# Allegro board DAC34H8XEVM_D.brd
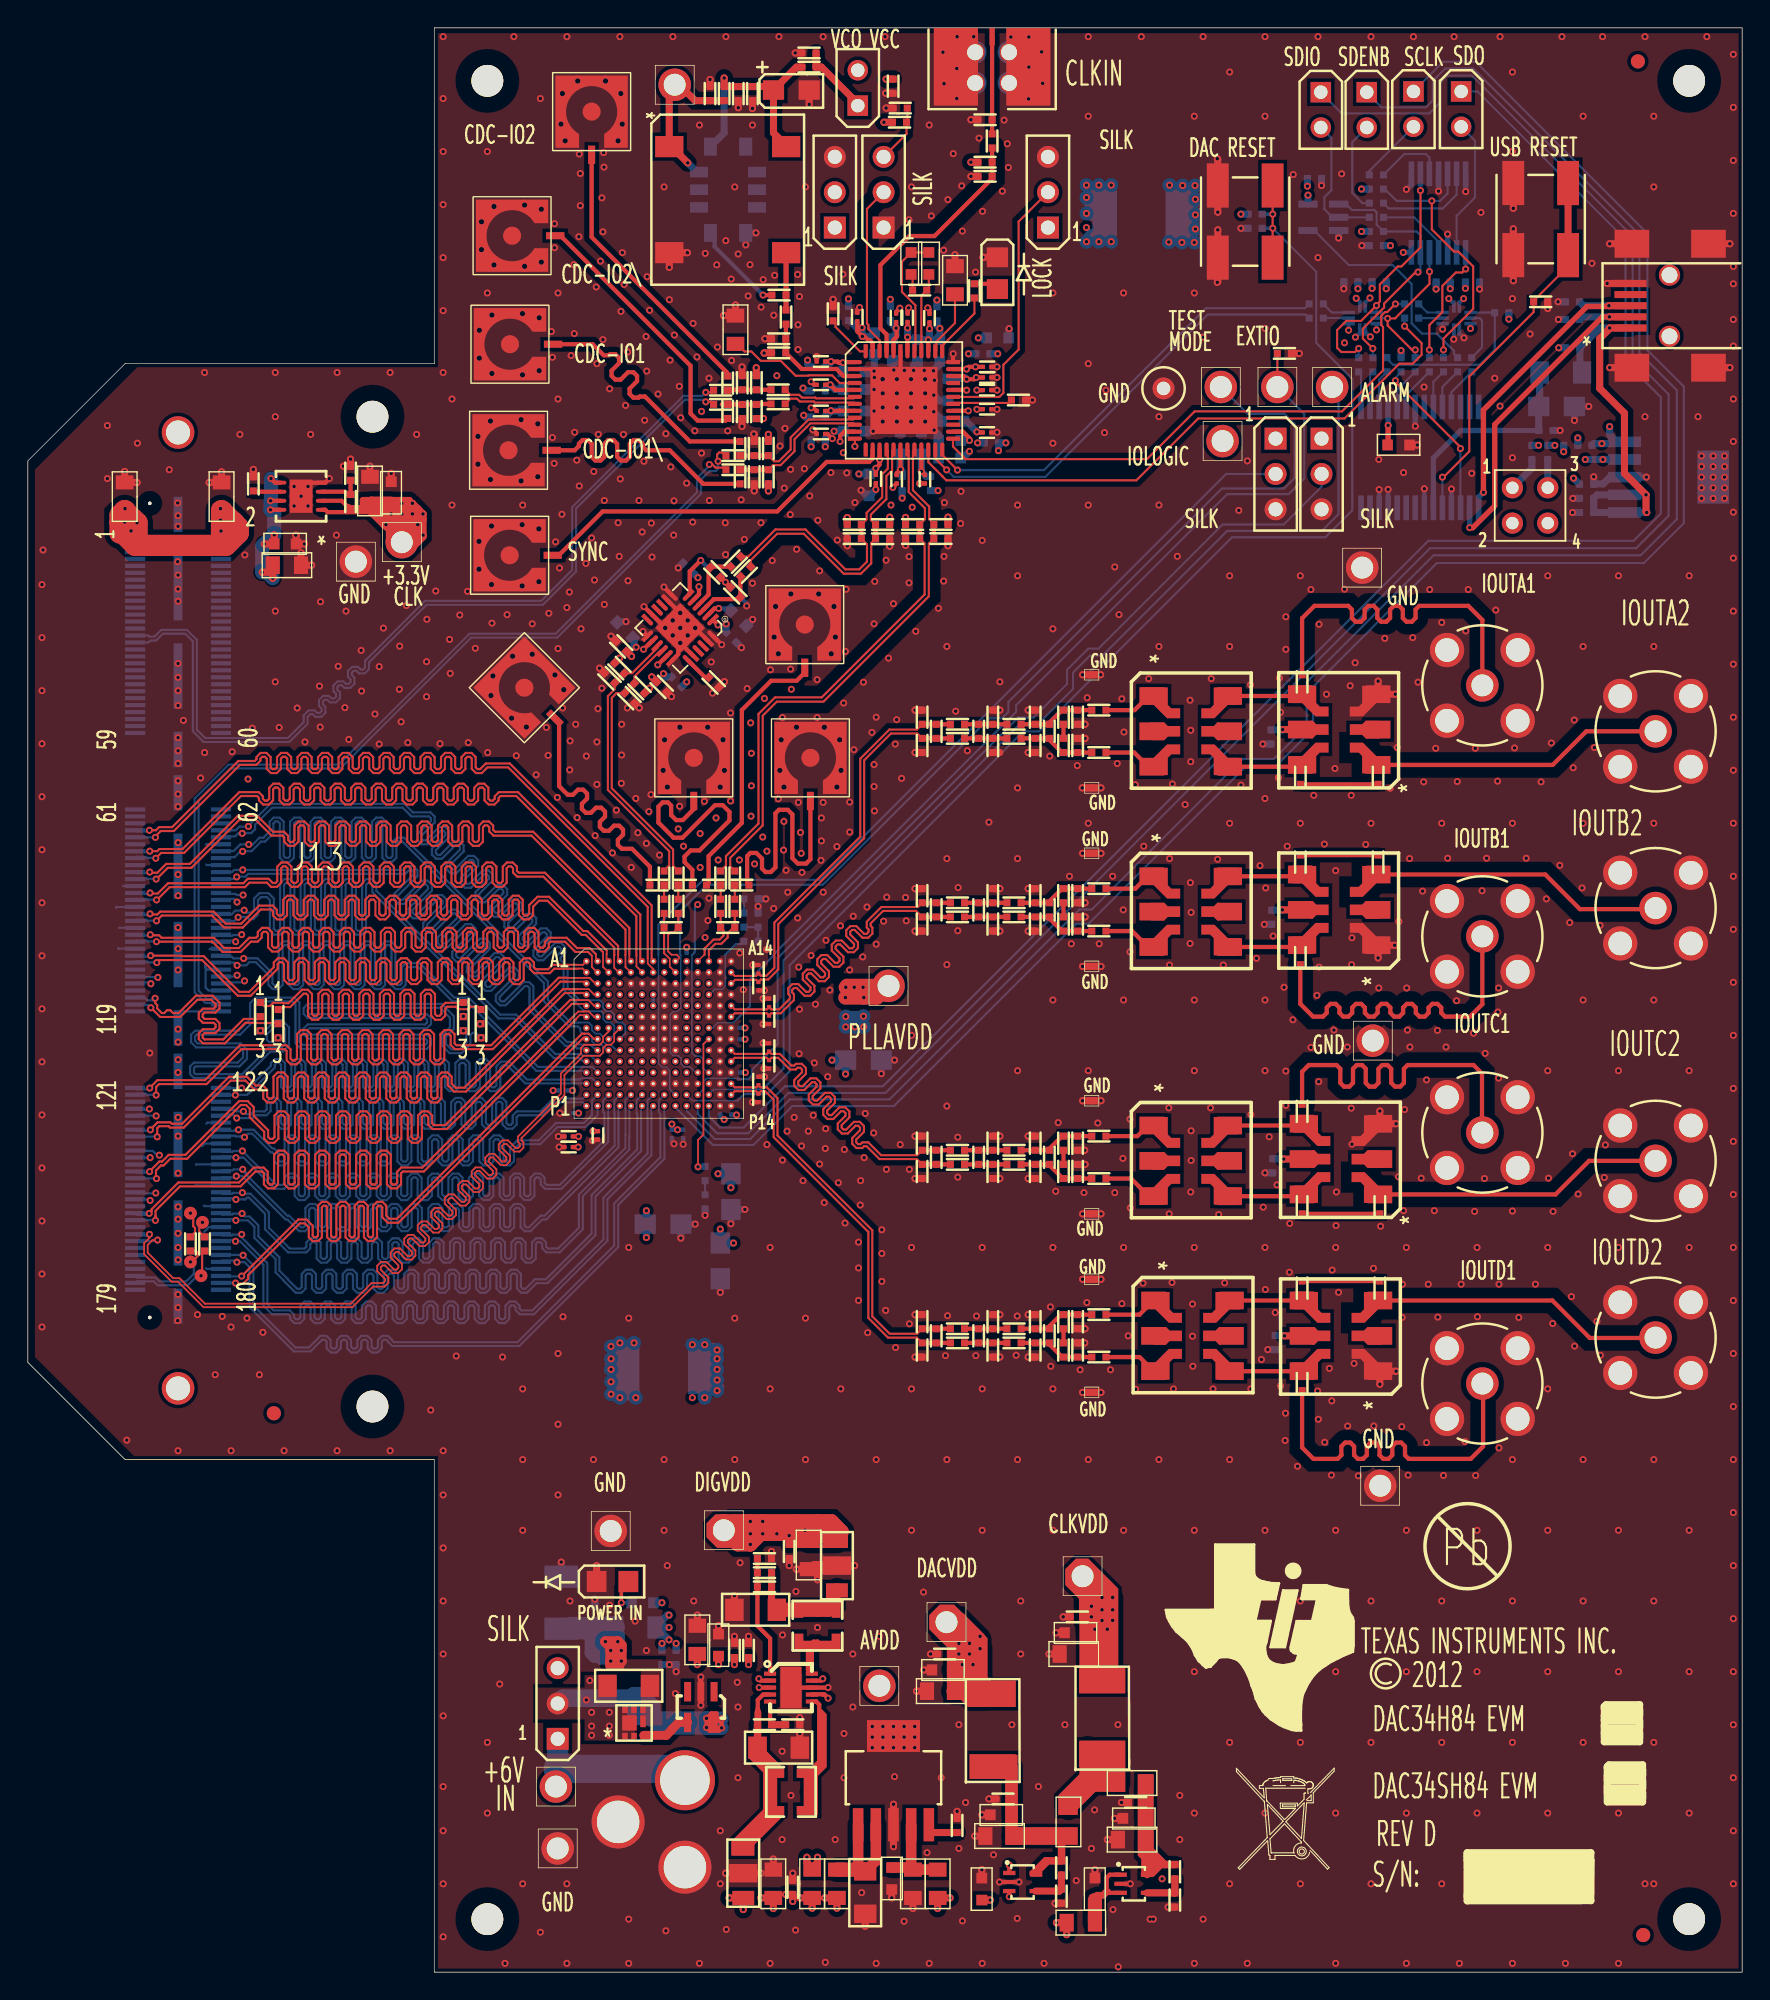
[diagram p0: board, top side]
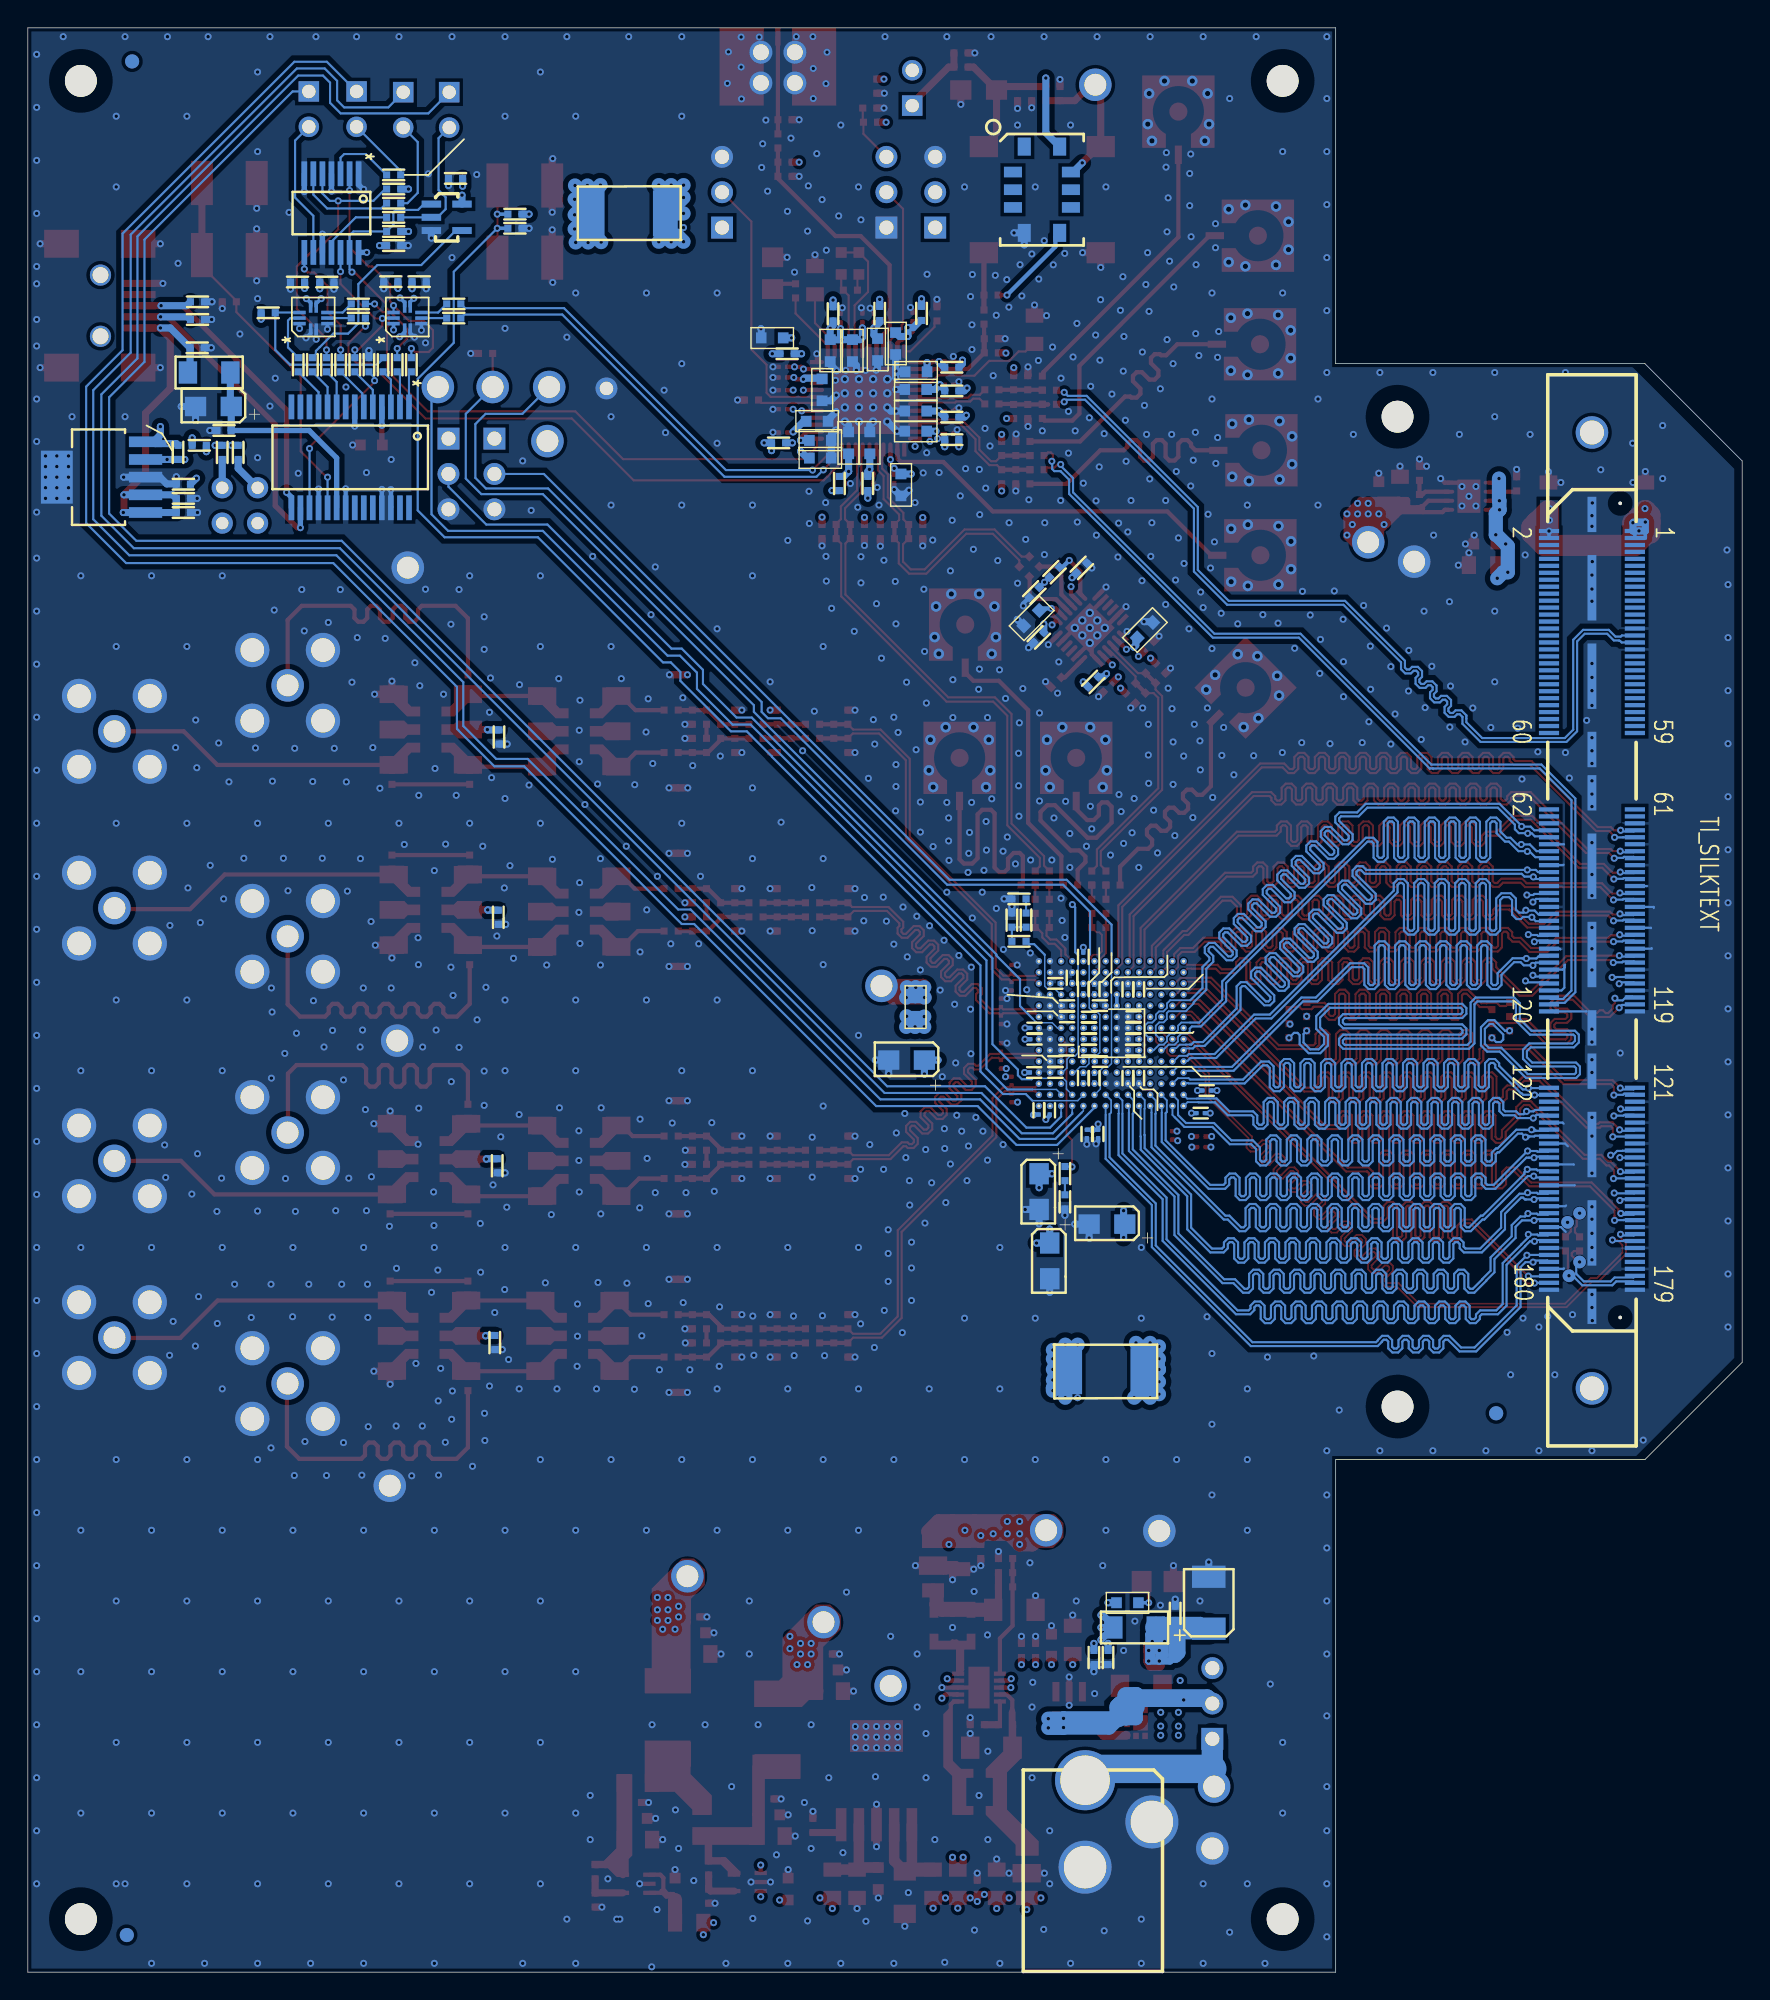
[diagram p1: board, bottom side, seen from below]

Outline 123.19 x 139.7 mm; copper layers: TOP, L2_GND, L3_PWR, L4_GND, L5_GND, L6_PWR, L7_GND, BOTTOM. Coordinates in mm from the lower left corner of the outline.
Outline path: 0,108.59 0,43.82 6.99,36.83 29.21,36.83 29.21,0 123.19,0 123.19,139.7 29.21,139.7 29.21,115.57 6.99,115.57 0,108.59

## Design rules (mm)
net group 50 OHM: nets N30997791 N30998469
net group DA0: nets DA0N DA0P
net group DA1: nets DA1N DA1P
net group DA2: nets DA2N DA2P
net group DA3: nets DA3N DA3P
net group DA4: nets DA4N DA4P
net group DA5: nets DA5N DA5P
net group DA6: nets DA6N DA6P
net group DA7: nets DA7N DA7P
net group DA8: nets DA8N DA8P
net group DA9: nets DA9N DA9P
net group DA10: nets DA10N DA10P
net group DA11: nets DA11N DA11P
net group DA12: nets DA12N DA12P
net group DA13: nets DA13N DA13P
net group DA14: nets DA14N DA14P
net group DA15: nets DA15N DA15P
net group DATACLK: nets DATACLKN DATACLKP
net group DATACLK-: nets DATACLK-N DATACLK-P
net group DB0: nets DB0N DB0P
net group DB1: nets DB1N DB1P
net group DB2: nets DB2N DB2P
net group DB3: nets DB3N DB3P
net group DB4: nets DB4N DB4P
net group DB5: nets DB5N DB5P
net group DB6: nets DB6N DB6P
net group DB7: nets DB7N DB7P
net group DB8: nets DB8N DB8P
net group DB9: nets DB9N DB9P
net group DB10: nets DB10N DB10P
net group DB11: nets DB11N DB11P
net group DB12: nets DB12N DB12P
net group DB13: nets DB13N DB13P
net group DB14: nets DB14N DB14P
net group DB15: nets DB15N DB15P
net group DCLK: nets DCLK-N DCLK-P
net group DP1: nets IOUTA1 IOUTA2
net group DP2: nets IOUTB1 IOUTB2
net group DP3: nets IOUTC1 IOUTC2
net group DP5: nets FIFO_OSTR FIFO_OSTRC
net group DP9: nets IOUTD1 IOUTD2
net group DP10: nets DCLKN DCLKP
net group FIFO_ISTR: nets FIFO_ISTRN FIFO_ISTRP
net group FPGA_CLKOUT: nets FPGA_CLKOUTN FPGA_CLKOUTP
net group FPGA_CLKOUT2: nets FPGA_CLKOUT2_N FPGA_CLKOUT2_P
net group PARITY: nets PARITYN PARITYP
net group PWR: nets +5V_USB N27288450
net group SYNC: nets SYNCN SYNCP

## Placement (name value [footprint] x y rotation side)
C1  .01uF  [0402]  45.72 76.71 90 top
C2  .01uF  [0402]  46.74 76.71 90 top
C3  .01uF  [0402]  49.78 76.71 90 top
C4  .01uF  [0402]  50.8 76.71 90 top
C5  .22uF  [0201]  50.88 64.64 180 bottom
C6  .22uF  [0201]  50.85 67.84 180 bottom
C7  .22uF  [0201]  47.35 64.24 270 bottom
C8  .22uF  [0201]  47.35 70.64 90 bottom
C9  .22uF  [0201]  48.51 69.44 0 bottom
C10  .22uF  [0201]  48.56 66.24 0 bottom
C11  .22uF  [0201]  50.85 67.03 180 bottom
C12  .22uF  [0201]  48.51 68.63 0 bottom
C13  .22uF  [0201]  46.15 65.43 180 bottom
C14  .22uF  [0201]  46.94 67.03 180 bottom
C15  .22uF  [0201]  50.55 61.93 90 bottom
C16  .22uF  [0201]  49.76 61.93 90 bottom
C17  .22uF  [0201]  46.94 66.24 180 bottom
C18  .22uF  [0201]  46.56 70.64 90 bottom
C19  .22uF  [0201]  46.56 64.24 270 bottom
C20  .22uF  [0201]  46.15 69.44 180 bottom
C21  .22uF  [0201]  46.94 67.84 180 bottom
C22  10uF  [TANT_A]  49.76 51.1 270 bottom
C23  .22uF  [0201]  46.94 68.63 180 bottom
C24  10uF  [TANT_A]  50.52 56.08 270 bottom
C25  .22uF  [0201]  40.97 60.12 270 top
C26  .22uF  [0201]  43.74 68.66 0 bottom
C27  .22uF  [0201]  38.91 61.72 180 bottom
C28  .22uF  [0201]  47.09 60.22 270 bottom
C29  .22uF  [0201]  38.48 63.35 180 bottom
C30  10uF  [TANT_A]  45.64 53.75 0 bottom
C31  .22uF  [0201]  43.76 66.24 0 bottom
C32  .22uF  [0201]  38.86 59.28 180 top
C33  .22uF  [0201]  46.28 60.22 270 bottom
C34  .1uF  [0402]  52.1 77.11 0 bottom
C35  1000pF  [0402]  52.48 75.72 90 bottom
C36  .1uF  [0201]  38.86 60.05 180 top
C37  .1uF  [0402]  90.42 116.31 0 top
C38  .22uF  [0201]  49.35 71.04 0 bottom
C39  .22uF  [0201]  49.35 65.43 0 bottom
C40  10uF  [TANT_A]  60.05 65.53 0 bottom
C41  .22uF  [0201]  43.76 67.03 0 bottom
C42  .22uF  [0201]  43.74 67.84 0 bottom
C43  .22uF  [0201]  44.15 64.24 270 bottom
C44  .22uF  [0201]  43.36 64.24 270 bottom
C45  .22uF  [0201]  43.36 70.61 90 bottom
C46  .22uF  [0201]  44.15 70.61 90 bottom
C47  1000pF  [0402]  88.06 125.3 180 bottom
C48  .1uF  [0201]  48.16 71.45 90 bottom
C49  .22uF  [0201]  47.35 72.95 270 bottom
C50  1000pF  [0402]  108.84 120.02 0 top
C51  .22uF  [0201]  49.35 64.64 0 bottom
C52  4.7uF  [0603]  63.47 122.77 270 top
C53  1000pF  [0402]  69.29 131.44 270 top
C54  .01uF  [0402]  50.78 99.22 135 bottom
C55  .27uF  [0603]  64.74 122.77 270 top
C56  .01uF  [0201]  63.22 118.87 90 top
C57  .01uF  [0201]  64.8 118.85 90 top
C58  .01uF  [0201]  62.39 118.87 90 top
C59  4.7uF  [0603]  63.93 116.51 270 bottom
C60  4.7uF  [0603]  65.53 116.51 270 bottom
C61  4.7uF  [0603]  62.13 116.59 270 bottom
C62  4.7uF  [0603]  42.91 96.42 135 bottom
C63  1uF  [0402]  57.86 119.02 270 top
C64  10uF  [0805]  66.62 121.56 270 top
C65  .01uF  [0201]  59.6 118.93 90 top
C66  4.7uF  [0603]  60.83 117.02 270 bottom
C67  .01uF  [0201]  56.99 114.05 180 top
C68  4.7uF  [0603]  59.39 113.72 0 bottom
C69  .01uF  [0201]  68.94 115.34 0 top
C70  .01uF  [0201]  68.94 114.58 0 top
C71  4.7uF  [0603]  66.12 113.69 270 bottom
C72  4.7uF  [0603]  69.7 117.42 0 bottom
C73  .01uF  [0201]  56.99 115.73 180 top
C74  4.7uF  [0603]  59.36 114.99 0 bottom
C75  10uF  [0805]  50.85 118.01 270 top
C76  .01uF  [0201]  68.93 110.62 0 top
C77  .01uF  [0201]  68.93 113.67 0 top
C78  .01uF  [0201]  68.93 112.3 0 top
C79  4.7uF  [0603]  66.24 110.06 180 bottom
C80  4.7uF  [0603]  66.47 111.43 180 bottom
C81  4.7uF  [0603]  66.24 108.79 180 bottom
C82  .01uF  [0201]  64.47 107.26 270 top
C83  4.7uF  [0603]  64.21 109.88 90 bottom
C84  .01uF  [0201]  56.99 110.52 180 top
C85  4.7uF  [0603]  59.39 110.72 0 bottom
C86  .01uF  [0201]  56.99 112.17 180 top
C87  4.7uF  [0603]  59.39 112.17 0 bottom
C88  .01uF  [0201]  62.43 107.26 270 top
C89  4.7uF  [0603]  62.69 109.88 90 bottom
C90  .01uF  [0402]  45.64 92.26 315 top
C91  10nF  [0402]  110.9 116.71 180 bottom
C92  .1uF  [0402]  109.22 110.77 0 bottom
C93  4.7uF  [TANT_A]  109.85 112.5 0 bottom
C94  .1uF  [0402]  97.23 121.46 0 bottom
C95  47pF  [0402]  110.87 118.75 180 bottom
C96  47pF  [0402]  110.87 120.02 180 bottom
C97  .1uF  [0402]  98.68 115.62 90 bottom
C98  .1uF  [0402]  92.58 128.88 0 bottom
C99  .01uF  [0402]  50.78 101.26 225 top
C100  .01uF  [0402]  51.5 100.54 225 top
C101  .01uF  [0402]  42.55 95.34 135 top
C102  .01uF  [0402]  50.63 95.81 315 bottom
C103  .01uF  [0402]  47.36 100.98 135 bottom
C104  4.7uF  [0603]  51.06 97.28 315 bottom
C111  1uF  [0603]  49.63 23.49 90 top
C112  .1uF  [0402]  50.77 23.24 90 top
C116  .1uF  [0402]  16.21 107.06 90 top
C117  1uF  [0603]  18.49 102.62 0 top
C118  1uF  [0603]  26.11 106.3 90 top
C127  .01uF  [0201]  60.93 107.29 270 top
C128  4.7uF  [0603]  60.45 106.86 270 bottom
C133  10uF  [0805]  53.57 6.35 90 top
C134  10uF  [0805]  56.11 29.97 270 top
C135  10uF  [0805]  18.62 101.09 0 top
C136  1uF  [0402]  111.89 105.89 180 bottom
C137  .1uF  [0402]  111.89 104.88 180 bottom
C138  15pF  [0402]  112.4 109.07 270 bottom
C139  .1uF  [0402]  94.95 121.46 180 bottom
C140  .1uF  [0402]  103.94 121.44 0 bottom
C141  .1uF  [0402]  101.57 121.44 180 bottom
C142  .1uF  [0402]  96.77 124.05 180 bottom
C143  10uF  [0805]  6.96 106.02 90 top
C144  10uF  [0805]  13.92 106.02 90 top
C145  10uF  [0805]  63.6 6.35 270 top
C146  10uF  [0805]  69.82 9.78 180 top
C147  10uF  [0805]  65.63 20.19 180 top
C148  10uF  [0805]  75.16 22.86 180 top
C149  10uF  [0805]  79.35 9.53 180 top
C152  47uF  [TANT_B]  38.33 26.54 90 bottom
C153  .1uF  [0402]  40.74 25.91 90 bottom
C154  1uF  [0402]  45.57 22.48 270 bottom
C155  10nF  [0402]  46.58 22.48 270 bottom
C161  10uF  [0805]  48.11 23.88 90 top
C162  10nF  [0402]  66.78 10.67 90 top
C163  2.2uF  [1206]  60.17 5.71 270 top
C164  1uF  [0603]  62.08 6.73 270 top
C165  22uF  [1206]  53.95 16.13 0 top
C166  33pF  [0402]  52.81 27.69 180 top
C167  22uF  [1206]  52.3 26.04 180 top
C169  2.2uF  [0603]  68.55 5.97 90 top
C170  1uF  [0603]  65.76 21.72 180 top
C177  .1uF  [0402]  54.48 118.79 270 top
C178  100pF  [0402]  52.07 134.85 270 top
C179  4.7uF  [0402]  62.18 135.38 270 top
C180  .1uF  [0402]  56.01 137.9 180 top
C181  10uF  [TANT_A]  54.86 135.23 0 top
C182  .1uF  [0402]  51.05 134.85 270 top
C215  10uF  [0805]  24.59 106.43 90 top
C233  10nF  [0402]  54.71 30.1 270 top
C234  10nF  [0402]  54.97 6.22 90 top
C237  10nF  [0402]  51.79 23.24 90 top
C238  1uF  [0603]  75.29 24.38 180 top
C240  2.2uF  [0603]  76.68 5.97 90 top
C242  10nF  [0402]  75.29 25.53 180 top
C243  10nF  [0402]  65.76 22.86 180 top
C244  1uF  [0603]  69.95 11.3 180 top
C245  10nF  [0402]  69.95 12.45 180 top
C246  1uF  [0603]  79.48 11.05 180 top
C247  10nF  [0402]  79.48 12.19 180 top
C250  2.2uF  [0603]  98.5 109.73 0 top
C251  CAP NP_1  [0402]  64.26 44.83 90 top
C252  CAP NP_1  [0402]  69.34 44.83 90 top
C253  CAP NP_1  [0402]  72.39 44.83 90 top
C254  3.3pF  [0402]  73.41 45.85 90 top
C255  3.3pF  [0402]  65.28 45.85 90 top
C256  3.3pF  [0402]  68.33 45.85 90 top
C257  CAP NP_1  [0402]  69.34 46.86 90 top
C258  CAP NP_1  [0402]  64.26 46.86 90 top
C259  CAP NP_1  [0402]  72.39 46.86 90 top
C260  CAP NP_1  [0402]  69.34 57.66 90 top
C261  CAP NP_1  [0402]  64.26 57.66 90 top
C262  CAP NP_1  [0402]  72.39 57.66 90 top
C263  3.3pF  [0402]  65.28 58.67 90 top
C264  3.3pF  [0402]  68.33 58.67 90 top
C265  3.3pF  [0402]  73.41 58.67 90 top
C266  CAP NP_1  [0402]  64.26 59.69 90 top
C267  CAP NP_1  [0402]  69.34 59.69 90 top
C268  CAP NP_1  [0402]  72.39 59.69 90 top
C269  CAP NP_1  [0402]  64.26 75.44 90 top
C270  CAP NP_1  [0402]  69.34 75.44 90 top
C271  CAP NP_1  [0402]  72.39 75.44 90 top
C272  3.3pF  [0402]  65.28 76.45 90 top
C273  3.3pF  [0402]  68.33 76.45 90 top
C274  3.3pF  [0402]  73.41 76.45 90 top
C275  CAP NP_1  [0402]  64.26 77.47 90 top
C276  CAP NP_1  [0402]  69.34 77.47 90 top
C277  CAP NP_1  [0402]  72.39 77.47 90 top
C278  CAP NP_1  [0402]  64.26 88.27 90 top
C279  CAP NP_1  [0402]  69.34 88.27 90 top
C280  CAP NP_1  [0402]  72.39 88.27 90 top
C281  3.3pF  [0402]  65.28 89.28 90 top
C282  3.3pF  [0402]  68.33 89.28 90 top
C283  3.3pF  [0402]  73.41 89.28 90 top
C284  CAP NP_1  [0402]  64.26 90.3 90 top
C285  CAP NP_1  [0402]  69.34 90.3 90 top
C286  CAP NP_1  [0402]  72.39 90.3 90 top
D1  LED green  [LED_0805]  69.67 122.07 90 top
D2  Blue  [LED_0805]  42.01 28.07 180 top
F3  2 AMP 63V FAST SMD  [1206]  43.18 20.57 0 top
FB1  1.5K @ 100MHz  [0603]  59.41 69.34 270 bottom
FB3  120  [0402]  61.98 119.05 270 bottom
FB4  1K  [0402]  65.33 119.02 270 bottom
FB5  120  [0402]  58.97 119.05 270 bottom
FB6  1K  [0402]  56.92 113.61 0 bottom
FB7  1K  [0402]  68.5 116.28 180 bottom
FB8  120  [0402]  56.92 115.32 0 bottom
FB9  120  [0402]  69.11 109.88 180 bottom
FB10  120  [0402]  64.87 107.09 90 bottom
FB11  120  [0402]  56.92 110.11 0 bottom
FB12  120  [0402]  56.92 111.73 0 bottom
FB13  120  [0402]  62.83 106.84 270 bottom
FB14  68 OHM @ 100MHz  [1206]  110.16 114.94 0 bottom
FB15  120  [0402]  46.72 92.62 315 bottom
FB20  68 OHM @ 100MHz  [1206]  43.66 24.76 180 bottom
FB22  1K  [1810]  45.69 43.18 180 bottom
FB24  1K  [1810]  80.01 126.37 0 bottom
FB25  1K  [0402]  56.26 136.88 0 top
FB30  27uF  [1206_BEAD_NFM31P]  58.14 29.21 90 top
FB31  27uF  [1206_BEAD_NFM31P]  51.41 7.11 270 top
FB34  1K  [1810]  69.32 17.4 90 top
FB35  1K  [1810]  77.19 18.29 90 top
J1  SMA_PCB_THVT  [SMA_THVT_312X312]  104.52 42.29 0 top
J2  SMA_PCB_THVT  [SMA_THVT_312X312]  116.97 45.59 0 top
J3  SMA_PCB_THVT  [SMA_THVT_312X312]  116.97 58.29 0 top
J4  SMA_PCB_THVT  [SMA_THVT_312X312]  104.52 60.33 0 top
J5  SMA_PCB_THVT  [SMA_THVT_312X312]  104.52 74.42 0 top
J6  SMA_PCB_THVT  [SMA_THVT_312X312]  116.97 76.45 0 top
J7  SMA_PCB_THVT  [SMA_THVT_312X312]  116.97 89.15 0 top
J8  SMA_PCB_THVT  [SMA_THVT_312X312]  104.52 92.46 0 top
J9  SMA_END_JACK_RND  [SMA_SMEL_218X247_096]  69.29 139.7 0 top
J10  SMP_PCB_SMT  [SMP_B120]  40.51 133.68 0 top
J11  SMP_PCB_SMT  [SMP_B120]  34.8 124.76 90 top
J12  SMP_PCB_SMT  [SMP_B120]  34.65 116.97 90 top
J13  CON, SMVT, 180POS, HS GND PLANE, QTH  [CON_SMVT_180POS_QTH_SAMTEC_RT1]  8.76 105.5 270 bottom
J14  USB_MINI_AB  [CON_SMRT_USBMNE20_F]  118.62 119.74 180 top
J15  SMP_PCB_SMT  [SMP_B120]  34.54 109.35 90 top
J18  CONN JACK PWR  [CON_RAPC722_JACK_THVT_3]  47.22 10.67 180 bottom
J19  SMP_PCB_SMT  [SMP_B120]  34.62 101.8 90 top
J20  SMP_PCB_SMT  [SMP_B120]  35.68 92.29 45 top
J21  SMP_PCB_SMT  [SMP_B120]  47.85 87.25 0 top
J22  SMP_PCB_SMT  [SMP_B120]  55.83 96.82 0 top
J23  SMP_PCB_SMT  [SMP_B120]  56.24 87.25 0 top
JP2  Jumper_1x3_100_430L  [HDR_THVT_1X3_100_M]  89.66 110.19 0 top
JP3  Jumper_1x3_100_430L  [HDR_THVT_1X3_100_M]  92.96 110.19 0 top
JP4  Jumper_1x3_100_430L  [HDR_THVT_1X3_100_M]  61.49 125.35 180 top
JP5  Jumper_1x3_100_430L  [HDR_THVT_1X3_100_M]  73.3 125.35 180 top
JP6  Jumper_1x3_100_430L  [HDR_THVT_1X3_100_M]  57.99 125.35 180 top
JP7  HEADER_1x2_100_430L  [HDR_THVT_1X2_100_M]  59.64 134.11 180 top
JP8  HEADER_1x2_100_430L  [HDR_THVT_1X2_100_M]  103 135.13 0 top
JP9  HEADER_1x2_100_430L  [HDR_THVT_1X2_100_M]  99.57 135.13 0 top
JP10  Jumper_1x3_100_430L  [HDR_THVT_1X3_100_M]  38.07 16.76 180 top
JP11  JUMPER_2X2  [HDR2X2_100CTR]  106.68 106.65 0 top
JP12  HEADER_1x2_100_430L  [HDR_THVT_1X2_100_M]  96.22 135.08 0 top
JP13  HEADER_1x2_100_430L  [HDR_THVT_1X2_100_M]  92.91 135.08 0 top
L25  2.2uH  [LPS3015]  54.84 12.95 180 top
L26  2.2uH  [LPS3015]  56.74 24.89 90 top
L27  0  [0402]  66.68 45.21 180 top
L28  0  [0402]  70.74 45.21 180 top
L29  0  [0402]  66.68 46.23 180 top
L30  0  [0402]  70.74 46.23 180 top
L31  0  [0402]  66.68 58.04 180 top
L32  0  [0402]  70.74 58.04 180 top
L33  0  [0402]  70.74 59.05 180 top
L34  0  [0402]  66.68 59.05 180 top
L35  0  [0402]  70.74 75.82 180 top
L36  0  [0402]  66.68 75.82 180 top
L37  0  [0402]  66.68 76.84 180 top
L38  0  [0402]  70.74 76.84 180 top
L39  0  [0402]  70.74 88.65 180 top
L40  0  [0402]  66.68 88.65 180 top
L41  0  [0402]  66.68 89.66 180 top
L42  0  [0402]  70.74 89.66 180 top
NOREF  -  []  745.39 141.78 0 top
NOREF#2  -  []  29.21 139.7 0 top
NOREF#3  -  [unnamed#2]  115.7 137.29 0 top
NOREF#4  -  []  -9.7 77.7 0 top
NOREF#5  -  []  2.68 111.26 0 top
NOREF#6  -  [unnamed#3]  33.02 135.89 0 top
NOREF#7  -  []  29.21 0 90 top
NOREF#8  -  [unnamed#2]  17.68 40.16 0 top
NOREF#9  -  [unnamed#3]  33.02 3.81 0 top
NOREF#10  -  []  29.21 0 0 top
NOREF#11  -  []  133.65 20.93 0 top
NOREF#12  -  []  0 43.82 0 top
NOREF#13  -  [unnamed#3]  24.77 40.64 0 top
NOREF#14  -  [unnamed#3]  119.38 3.81 0 top
NOREF#15  -  []  0 43.82 0 top
NOREF#16  -  []  70.83 71.54 0 top
NOREF#17  -  []  33.02 3.81 90 top
NOREF#18  -  []  29.21 0 90 top
NOREF#19  -  []  -120.65 -165.1 0 top
NOREF#20  -  []  90.3 11.18 0 top
NOREF#21  -  []  -16.38 134.62 0 top
NOREF#22  -  [unnamed#2]  116.08 2.67 0 top
NOREF#23  -  [unnamed#3]  119.38 135.89 0 top
NOREF#24  -  []  33.02 3.81 90 top
NOREF#25  -  []  -128.27 -60.96 0 top
NOREF#26  -  [unnamed#3]  24.77 111.76 0 top
NOREF#27  -  [unnamed#2]  116.08 2.67 180 bottom
NOREF#28  -  [unnamed#2]  115.7 137.29 180 bottom
NOREF#29  -  [unnamed#2]  17.68 40.16 180 bottom
Q3  CSD17313Q2  [SON_8_2MMX2MM_0P65MM]  43.56 17.91 0 top
R4  0  [0402]  91.57 42.16 270 top
R5  100  [0402]  46.36 75.06 0 top
R6  100  [0402]  75.44 44.58 270 top
R7  49.9  [0402]  74.42 44.83 90 top
R9  0  [0402]  89.64 45.11 270 bottom
R10  100  [0402]  75.44 46.61 270 top
R12  0  [0402]  89.46 57.81 270 bottom
R13  0  [0402]  97.16 49.28 90 top
R14  0  [0402]  89.38 75.67 270 bottom
R15  100  [0402]  50.42 75.06 0 top
R16  0  [0402]  91.57 49.28 90 top
R18  0  [0402]  89.33 88.62 270 bottom
R20  0  [0402]  91.57 54.86 270 top
R21  100  [0402]  75.44 57.4 270 top
R22  49.9  [0402]  74.42 57.66 90 top
R23  100  [0402]  75.44 59.44 270 top
R24  0  [0402]  97.16 55.12 90 top
R25  0  [0402]  91.57 61.98 90 top
R28  0  [0402]  91.44 72.77 270 top
R29  100  [0402]  75.44 75.18 270 top
R30  49.9  [0402]  74.42 75.44 90 top
R31  100  [0402]  75.44 77.22 270 top
R32  0  [0402]  97.03 79.88 90 top
R33  49.9  [0201]  52.5 64.03 90 top
R34  0  [0402]  91.44 79.88 90 top
R35  49.9  [0201]  52.5 62.81 270 top
R36  0  [0402]  91.44 85.73 270 top
R37  100  [0402]  75.44 88.01 270 top
R38  49.9  [0402]  74.42 88.27 90 top
R39  100  [0402]  75.44 90.04 270 top
R40  0  [0402]  97.03 85.98 90 top
R41  49.9  [0201]  53.26 65.23 270 top
R42  0  [0402]  91.57 92.84 90 top
R43  1K  [0402]  51.46 75.72 90 bottom
R44  1.27K  [0402]  48.67 57.25 270 bottom
R45  10  [0402]  48.67 55.22 270 bottom
R46  1K  [0402]  88.06 126.31 180 bottom
R47  82.5  [0402]  68.91 130.05 0 top
R48  1.1K  [0402]  63.96 120.85 180 top
R49  49.9  [0402]  68.91 133.1 0 top
R50  130  [0402]  68.66 129.03 180 top
R51  82.5  [0402]  62.76 132.92 0 top
R52  301  [0402]  68.02 120.93 90 top
R53  130  [0402]  52.35 114.07 270 top
R54  22.1  [0402]  54.04 113.69 0 top
R55  0  [0402]  71.06 112.96 180 top
R56  82.5  [0402]  51.34 114.33 90 top
R57  130  [0402]  52.35 112.26 90 top
R58  22.1  [0402]  54.04 112.68 0 top
R59  82.5  [0402]  51.34 112.01 270 top
R60  130  [0402]  53.21 107.57 90 top
R61  130  [0402]  53.21 109.35 270 top
R62  130  [0402]  65.49 104.02 180 top
R63  130  [0402]  63.71 104.02 0 top
R64  82.5  [0402]  52.2 107.31 270 top
R65  82.5  [0402]  52.2 109.6 90 top
R66  150  [0402]  65.74 103 0 top
R67  150  [0402]  63.45 103 180 top
R68  130  [0402]  61.3 104.01 180 top
R69  130  [0402]  59.51 104.01 0 top
R70  0  [0402]  49.32 100.68 135 bottom
R71  150  [0402]  61.55 102.99 0 top
R72  150  [0402]  59.26 103 180 top
R73  10K  [0402]  105.79 119.23 180 bottom
R74  10K  [0402]  97.03 128.12 0 bottom
R75  22.1  [0402]  95.63 115.37 270 bottom
R76  22.1  [0402]  99.69 115.37 270 bottom
R77  22.1  [0402]  97.66 115.37 270 bottom
R78  22.1  [0402]  103.76 115.37 270 bottom
R79  22.1  [0402]  96.65 115.37 270 bottom
R80  22.1  [0402]  101.73 115.37 270 bottom
R81  22.1  [0402]  102.74 115.37 270 bottom
R82  22.1  [0402]  100.71 115.37 270 bottom
R83  10K  [0402]  97.03 125.07 0 bottom
R84  100  [0402]  96.77 129.13 180 bottom
R85  100  [0402]  92.46 119.86 180 bottom
R86  100  [0402]  96.77 127.1 180 bottom
R87  100  [0402]  96.77 126.09 180 bottom
R88  0  [0402]  49.91 113.67 0 top
R89  130  [0402]  43.86 92.35 135 top
R90  150  [0402]  43.32 91.45 315 top
R91  130  [0402]  42.6 93.6 315 top
R92  150  [0402]  41.71 93.06 135 top
R93  0  [0402]  49.91 112.65 0 top
R94  49.9  [0201]  53.26 66.45 90 top
R95  0  [0402]  53.85 120.5 180 top
R96  49.9  [0201]  53.26 69.65 90 top
R97  49.9  [0201]  53.26 68.43 270 top
R98  49.9  [0201]  52.5 70.84 270 top
R99  49.9  [0402]  74.42 46.86 90 top
R100  49.9  [0402]  74.42 59.69 90 top
R101  49.9  [0402]  74.42 77.47 90 top
R102  49.9  [0402]  74.42 90.3 90 top
R103  130  [0402]  62.81 133.93 0 top
R104  0  [0402]  77.09 44.2 0 top
R105  0  [0402]  77.09 47.24 0 top
R106  0  [0402]  77.09 57.02 0 top
R107  0  [0402]  77.09 60.07 0 top
R108  0  [0402]  77.09 74.8 0 top
R109  0  [0402]  77.09 77.85 0 top
R110  0  [0402]  77.09 87.63 0 top
R111  0  [0402]  77.09 90.68 0 top
R112  49.9  [0201]  52.5 72.06 90 top
R116  0  [0402]  50.55 108.97 180 top
R117  0  [0402]  50.55 107.95 180 top
R120  0  [0402]  50.29 112.27 90 top
R121  0  [0402]  50.29 114.05 270 top
R122  0  [0402]  45.34 78.11 0 top
R123  0  [0402]  47.12 78.11 180 top
R124  0  [0402]  49.4 78.11 0 top
R125  0  [0402]  51.18 78.11 180 top
R126  0  [0805]  75.67 3.56 180 top
R127  0  [0805]  79.35 13.59 180 top
R128  0  [0805]  74.78 10.79 270 top
R129  0  [0402]  51.18 109.35 270 top
R130  0  [0402]  51.18 107.31 270 top
R131  60.4K  [0402]  49.38 92.58 315 top
R133  0  [0402]  51.84 74.07 180 bottom
R134  30.1K  [0402]  112.14 106.91 0 bottom
R135  51.1K  [0402]  111 109.7 0 bottom
R136  19.6K  [0402]  109.22 109.07 270 bottom
R137  82K  [0402]  108.08 109.07 270 bottom
R138  100  [0402]  92.46 118.85 180 bottom
R139  100  [0402]  99.31 119.86 180 bottom
R140  100  [0402]  99.31 118.85 180 bottom
R143  10K  [0603]  44.17 26.54 0 bottom
R145  0  [0805]  56.36 6.35 270 top
R146  0  [0805]  58.14 6.35 90 top
R147  0  [0805]  65.38 6.35 270 top
R148  750K  [0402]  52.81 17.78 180 top
R149  0  [0402]  45.72 78.49 270 top
R150  191K  [0402]  53.06 28.7 0 top
R151  150K  [0402]  54.84 17.78 180 top
R152  0  [0402]  46.74 78.49 270 top
R153  182K  [0402]  52.81 29.72 180 top
R154  0  [0402]  49.78 78.49 270 top
R155  0  [0402]  50.8 78.49 270 top
R156  0  [0402]  11.68 52.45 90 top
R157  0  [0402]  12.7 52.45 90 top
R164  10K  [0402]  49.02 134.85 270 top
R165  10K  [0402]  50.04 135.1 90 top
R166  10K  [0402]  54.08 116.35 0 top
R167  10K  [0402]  54.08 117.36 0 top
R168  10K  [0402]  23.19 107.57 270 top
R170  30.9K  [0402]  23.19 105.54 270 top
R206  49.9  [0402]  50.75 99.23 135 top
R207  49.9  [0402]  49.31 100.67 135 top
R221  174K  [0402]  82.42 7.34 90 top
R257  174K  [0402]  74.27 7.62 90 top
R315  330K  [0402]  82.42 5.31 90 top
R316  330K  [0402]  74.27 5.59 90 top
SJP9  SMT Jumper_1x3  [0201_SMD_JUMPER3X1]  16.71 68.66 90 top
SJP10  SMT Jumper_1x3  [0201_SMD_JUMPER3X1]  17.98 68.15 90 top
SJP11  SMT Jumper_1x3  [0201_SMD_JUMPER3X1]  31.29 68.66 90 top
SJP12  SMT Jumper_1x3  [0201_SMD_JUMPER3X1]  32.56 68.15 90 top
SW1  SW RESET  [SW_SMVT_RESET]  87.48 125.78 0 top
SW2  USB RESET  [SW_SMVT_RESET]  108.71 125.96 0 top
T1  ADT4-1WT  [TFMR_6_RF_DUAL_FOOTPRINT]  94.36 45.72 90 top
T2  ADT4-1WT  [TFMR_6_RF_DUAL_FOOTPRINT]  94.36 58.42 90 top
T3  ADT4-1WT  [TFMR_6_RF_DUAL_FOOTPRINT]  94.23 76.33 90 top
T4  ADT4-1WT  [TFMR_6_RF_DUAL_FOOTPRINT]  94.23 89.28 90 top
T8  ETC1-1-13  [TFMR_6_RF_DUAL_FOOTPRINT]  83.69 45.72 270 top
T9  ETC1-1-13  [TFMR_6_RF_DUAL_FOOTPRINT]  83.57 58.29 270 top
T10  ETC1-1-13  [TFMR_6_RF_DUAL_FOOTPRINT]  83.57 76.2 270 top
T11  ETC1-1-13  [TFMR_6_RF_DUAL_FOOTPRINT]  83.57 89.15 270 top
TP1  Testloop_Black  [TESTPOINT_62DIA]  41.88 31.7 0 top
TP2  Testloop_White  [TESTPOINT_62DIA]  89.79 113.89 180 top
TP3  Testloop_Black  [TP_THVT_060_RND]  81.61 113.79 0 top
TP4  Testloop_White  [TESTPOINT_62DIA]  85.72 113.89 0 top
TP5  Testloop_White  [TESTPOINT_62DIA]  93.73 113.89 180 top
TP6  Testloop_Black  [TESTPOINT_62DIA]  95.89 100.91 0 top
TP7  Testloop_Black  [TESTPOINT_62DIA]  97.18 34.95 0 top
TP8  Testloop_Black  [TESTPOINT_62DIA]  23.57 101.35 0 top
TP9  Testloop_Black  [TESTPOINT_62DIA]  96.65 66.93 0 top
TP12  Testloop_Red  [TESTPOINT_62DIA]  37.95 13.34 0 top
TP13  Testloop_Black  [TESTPOINT_62DIA]  38.07 8.89 0 top
TP14  Testloop_White  [TESTPOINT_62DIA]  46.48 135.61 0 top
TP15  Testloop_Red  [TESTPOINT_62DIA]  50.01 31.75 90 top
TP16  Testloop_Red  [TESTPOINT_62DIA]  61.19 20.57 0 top
TP17  Testloop_Red  [TESTPOINT_62DIA]  26.87 102.74 270 top
TP18  Testloop_Red  [TESTPOINT_62DIA]  66.01 25.15 0 top
TP19  Testloop_Red  [TESTPOINT_62DIA]  75.79 28.45 0 top
TP25  Testloop_White  [TESTPOINT_62DIA]  85.85 110.01 0 top
TP26  Testloop_White  [TESTPOINT_62DIA]  61.85 70.87 0 top
TP27  GND PAD  [TESTPAD20_30]  76.45 80.39 0 top
TP28  GND PAD  [TESTPAD20_30]  76.45 72.26 0 top
TP29  GND PAD  [TESTPAD20_30]  76.45 41.66 0 top
TP30  GND PAD  [TESTPAD20_30]  76.45 49.78 0 top
TP31  GND PAD  [TESTPAD20_30]  76.45 93.22 180 top
TP32  GND PAD  [TESTPAD20_30]  76.45 85.09 0 top
TP33  GND PAD  [TESTPAD20_30]  76.45 62.61 0 top
TP34  GND PAD  [TESTPAD20_30]  76.45 54.48 0 top
U1  DAC34H84  [BGA14X14_PT8MM]  45.34 67.44 180 top
U2  CDCE62005  [QFN48_RGZ_RTC]  62.96 112.93 0 top
U3  FT245RL  [SSOP_28_413X220_26]  100.03 108.84 270 bottom
U4  74AVC2T245  [QFN10_RSW]  95.91 118.85 90 bottom
U5  74AVC2T245  [QFN10_RSW]  102.67 118.85 90 bottom
U6  CDCP1803  [QFN24_RGE_RTW]  46.88 96.58 225 top
U9  74LVC125A  [TSSOP_14_201X177_26]  101.37 126.39 270 bottom
U10  74LVC1G126  [DBV5]  93.09 126.09 180 bottom
U11  TPS62420  [SON_DRC_10]  54.84 20.45 0 top
U12  TPS79633  [SOT_223_6_TG]  62.84 13.97 0 top
U13  TPS71701  [SC70_DCK_G5]  71.48 6.48 0 top
U15  TPS7A8001DRB  [SON_8_124X124_PWRPAD_DRB]  19.63 106.05 180 top
U16  TCXO 19.2MHz  [SMD_XTAL_7X5MM_D75ASERIES]  50.32 128.07 180 bottom
U17  TCXO 19.2MHz  [OSC_4_SM_460X386]  50.29 127.36 270 top
U20  TPS79601  [SOT_223_6_TG]  118.11 108.05 90 bottom
U21  TPS2400  [DBV5]  48.36 19.05 270 top
U22  TPS71701  [SC70_DCK_G5]  79.48 6.35 0 top

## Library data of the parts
C1-C4 C34-C37 C47 C48 C50 C52 C53 C55-C90 C92 C94 C97-C104 C127 C128 C137 C139-C142 C154 C155 C165 C167 C169 C177 C178 C180 C182 C240 C250 = CAP NP_1: tolerance: 10%
C5-C10 C12-C19 C21 C25-C29 C31-C33 C38 C41 C43 C45 C164 C170 C179 C238 C244 C246 = CAP NP_1: tolerance: 20%
C11 C20 C23 C39 C42 C44 C46 C49 C51 = CAP0402_0: tolerance: 20%
C22 C24 C30 C40 = CAP POL-B_10uF_10V
C54 C112 C116 C133 C134 C143-C149 C153 C161 = CAP NP: tolerance: 10%
C91 = CAP0603: tolerance: 10%
C93 = CAP POL-B_10uF_10V: tolerance: 10%
C95 C96 = CAP0603: tolerance: 5%
C111 C117 C118 = CAP NP_2: tolerance: 20%
C135 C215 = CAP0201: tolerance: 20%
C136 = CAP NP_2: tolerance: 10%
C138 = CAP0603: tolerance: 2%
C152 = CAP POL: tolerance: 10%
C162 C233 C234 C237 C242 C243 C245 C247 = CAPACITOR_NP_4: tolerance: 10%
C163 = CAP POL-B: tolerance: 10%
C166 = CAP NP_1: tolerance: 2%
C181 = CAP POL-B_10uF_10V: tolerance: 20%
C251-C286 = CAP NP_1: tolerance: .25pF
D1 D2 = LED
F3 = FUSE/SM
FB1 FB3-FB15 FB20 FB25 = FERRITE_BEAD
FB22 FB24 FB34 FB35 = FERRITE_BEAD_0402_H
FB30 FB31 = BEAD_NFM31P
J1-J8 = SMA_PCB_THVT_142-0701-201_REC
J9 = SMA-END_JACK_142-0761-801_ROUND
J10-J12 J15 J19-J23 = SMP_PLUG_SMT
J13 = CON_SMVT_180POS_QTH_SAMTEC
J14 = USB_MINI_AB_MNE20-5G5P10
J18 = CONN JACK PWR
JP2-JP6 JP10 SJP9-SJP12 = Jumper_1x3_100_0
JP7-JP9 JP12 JP13 = JUMPER_1x2_100
JP11 = JUMPER_3X2_SMT_0
L25 L26 = IND1206
L27-L42 = IND0603_0: tolerance: 5%
Q3 = PWR_MOSFET_CSD17313Q2
R4 R9 R12-R14 R16 R18 R20 R24 R25 R28 R32 R34 R36 R40 R42 R55 R70 R88 R93 R95 R104-R111 R116 R117 R120-R125 R129 R130 R133 R145-R147 R149 R152 R154-R157 = R: tolerance: 5%
R5 R15 R143 = RES0603: tolerance: 1%
R6 R10 R21 R23 R29 R31 R33 R35 R37 R39 R41 R47-R53 R56 R57 R59-R69 R71-R74 R83-R87 R89-R92 R94 R96-R98 R103 R112 R131 R134-R140 R148 R150 R151 R153 R164-R168 R170 R221 R257 R315 R316 = R: tolerance: 1%
R7 R22 R30 R38 R99-R102 = Res_0603: tolerance: 1%
R43-R46 R54 R58 R75-R82 = R_0: tolerance: 1%
R126-R128 = RES0603: tolerance: 5%
R206 R207 = RESISTOR: tolerance: 1%
SW1 SW2 = SPST_PB_KT11P3JM_5
T1-T4 = ADT4-1T_0
T8-T11 = TFMR_5_ETC1-1-13_4
TP1-TP9 TP12-TP19 TP25 TP26 = TESTLOOP_BLACK
TP27-TP34 = TEST POINT_0
U1 = DAC34H84
U2 = ARES_0
U3 = FT245RL_0
U4 U5 = 74AVC2T245
U6 = CDCM1804_MLF24_3
U9 = 74LVC125A
U10 = 74LVC1G126
U11 = TPS62420_SON10_1
U12 U20 = TPS79633DCQ_1
U13 U22 = TPS79633DCQ_2
U15 = TPS7A8001DRB
U16 = OSC-VECTRON_2
U17 = OSC-VECTRON_0
U21 = TPS2400

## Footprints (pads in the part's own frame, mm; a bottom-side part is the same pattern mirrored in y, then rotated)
0201
  rect 0.305x0.305 smd: 1(-0.305,0) 2(0.305,0)
0201_SMD_JUMPER3X1
  rect 0.508x0.508 smd: 1(1.016,0) 2(0,0) 3(-1.016,0)
0402
  rect 0.508x0.508 smd: 1(-0.635,0) 2(0.381,0)
0603
  rect 0.762x0.787 smd: 1(-0.787,0) 2(0.787,0)
0805
  rect 1.016x1.27 smd: 1(-1.016,0) 2(1.016,0)
1206
  rect 1.321x1.6 smd: 1(-1.524,0) 2(1.524,0)
1206_BEAD_NFM31P
  rect 1.016x1.575 smd: 1(-1.778,0) 3(1.778,0)
  rect 1.321x2.032 smd: 2(0,0)
1810
  rect 1.778x3.302 smd: 1(-2.629,0) 2(2.629,0)
BGA14X14_PT8MM
  round 0.457 hole 0.203: A1(5.2,-5.2) A2(4.4,-5.2) A3(3.6,-5.2) A4(2.8,-5.2) A5(2,-5.2) A6(1.2,-5.2) A7(0.4,-5.2) A8(-0.4,-5.2) A9(-1.2,-5.2) A10(-2,-5.2) A11(-2.8,-5.2) A12(-3.6,-5.2) A13(-4.4,-5.2) A14(-5.2,-5.2) B1(5.2,-4.4) B2(4.4,-4.4) B3(3.6,-4.4) B4(2.8,-4.4) B5(2,-4.4) B6(1.2,-4.4) B7(0.4,-4.4) B8(-0.4,-4.4) B9(-1.2,-4.4) B10(-2,-4.4) B11(-2.8,-4.4) B12(-3.6,-4.4) B13(-4.4,-4.4) B14(-5.2,-4.4) C1(5.2,-3.6) C2(4.4,-3.6) C3(3.6,-3.6) C4(2.8,-3.6) C5(2,-3.6) C6(1.2,-3.6) C7(0.4,-3.6) C8(-0.4,-3.6) C9(-1.2,-3.6) C10(-2,-3.6) C11(-2.8,-3.6) C12(-3.6,-3.6) C13(-4.4,-3.6) C14(-5.2,-3.6) D1(5.2,-2.8) D2(4.4,-2.8) D3(3.6,-2.8) D4(2.8,-2.8) D5(2,-2.8) D6(1.2,-2.8) D7(0.4,-2.8) D8(-0.4,-2.8) D9(-1.2,-2.8) D10(-2,-2.8) D11(-2.8,-2.8) D12(-3.6,-2.8) D13(-4.4,-2.8) D14(-5.2,-2.8) E1(5.2,-2) E2(4.4,-2) E3(3.6,-2) E4(2.8,-2) E5(2,-2) E6(1.2,-2) E7(0.4,-2) E8(-0.4,-2) E9(-1.2,-2) E10(-2,-2) E11(-2.8,-2) E12(-3.6,-2) E13(-4.4,-2) E14(-5.2,-2) F1(5.2,-1.2) F2(4.4,-1.2) F3(3.6,-1.2) F4(2.8,-1.2) F5(2,-1.2) F6(1.2,-1.2) F7(0.4,-1.2) F8(-0.4,-1.2) F9(-1.2,-1.2) F10(-2,-1.2) F11(-2.8,-1.2) F12(-3.6,-1.2) F13(-4.4,-1.2) F14(-5.2,-1.2) G1(5.2,-0.4) G2(4.4,-0.4) G3(3.6,-0.4) G4(2.8,-0.4) G5(2,-0.4) G6(1.2,-0.4) G7(0.4,-0.4) G8(-0.4,-0.4) G9(-1.2,-0.4) G10(-2,-0.4) G11(-2.8,-0.4) G12(-3.6,-0.4) G13(-4.4,-0.4) G14(-5.2,-0.4) H1(5.2,0.4) H2(4.4,0.4) H3(3.6,0.4) H4(2.8,0.4) H5(2,0.4) H6(1.2,0.4) H7(0.4,0.4) H8(-0.4,0.4) H9(-1.2,0.4) H10(-2,0.4) H11(-2.8,0.4) H12(-3.6,0.4) H13(-4.4,0.4) H14(-5.2,0.4) J1(5.2,1.2) J2(4.4,1.2) J3(3.6,1.2) J4(2.8,1.2) J5(2,1.2) J6(1.2,1.2) J7(0.4,1.2) J8(-0.4,1.2) J9(-1.2,1.2) J10(-2,1.2) J11(-2.8,1.2) J12(-3.6,1.2) J13(-4.4,1.2) J14(-5.2,1.2) K1(5.2,2) K2(4.4,2) K3(3.6,2) K4(2.8,2) K5(2,2) K6(1.2,2) K7(0.4,2) K8(-0.4,2) K9(-1.2,2) K10(-2,2) K11(-2.8,2) K12(-3.6,2) K13(-4.4,2) K14(-5.2,2) L1(5.2,2.8) L2(4.4,2.8) L3(3.6,2.8) L4(2.8,2.8) L5(2,2.8) L6(1.2,2.8) L7(0.4,2.8) L8(-0.4,2.8) L9(-1.2,2.8) L10(-2,2.8) L11(-2.8,2.8) L12(-3.6,2.8) L13(-4.4,2.8) L14(-5.2,2.8) M1(5.2,3.6) M2(4.4,3.6) M3(3.6,3.6) M4(2.8,3.6) M5(2,3.6) M6(1.2,3.6) M7(0.4,3.6) M8(-0.4,3.6) M9(-1.2,3.6) M10(-2,3.6) M11(-2.8,3.6) M12(-3.6,3.6) M13(-4.4,3.6) M14(-5.2,3.6) N1(5.2,4.4) N2(4.4,4.4) N3(3.6,4.4) N4(2.8,4.4) N5(2,4.4) N6(1.2,4.4) N7(0.4,4.4) N8(-0.4,4.4) N9(-1.2,4.4) N10(-2,4.4) N11(-2.8,4.4) N12(-3.6,4.4) N13(-4.4,4.4) N14(-5.2,4.4) P1(5.2,5.2) P2(4.4,5.2) P3(3.6,5.2) P4(2.8,5.2) P5(2,5.2) P6(1.2,5.2) P7(0.4,5.2) P8(-0.4,5.2) P9(-1.2,5.2) P10(-2,5.2) P11(-2.8,5.2) P12(-3.6,5.2) P13(-4.4,5.2) P14(-5.2,5.2)
CON_RAPC722_JACK_THVT_3
  round 4.318 hole 3.556: 1(0,3.124)
  round 3.81 hole 3.048: 2(0,-3.124) 3(4.801,0.127)
CON_SMRT_USBMNE20_F
  round 1.524 hole 1.143 unplated: (0.65,2.2) (0.65,-2.2)
  rect 2.311x0.508 smd: 1(3.45,1.6) 2(3.45,0.8) 3(3.45,0) 4(3.45,-0.8) 5(3.45,-1.6)
  rect 2.489x2.007 smd: 6(-2.15,-4.45) 7(3.35,-4.45) 8(3.35,4.45) 9(-2.15,4.45)
CON_SMVT_180POS_QTH_SAMTEC_RT1
  round 2.337 hole 1.727: (-5.123,-2.032) (63.558,-2.032)
  round 0.254 hole 1.016 unplated: (-0.03,0) (58.466,0)
  rect 0.305x1.448 smd: 1(1.958,1.054) 2(1.958,-5.118) 3(2.459,1.054) 4(2.459,-5.118) 5(2.959,1.054) 6(2.959,-5.118) 7(3.459,1.054) 8(3.459,-5.118) 9(3.96,1.054) 10(3.96,-5.118) 11(4.46,1.054) 12(4.46,-5.118) 13(4.961,1.054) 14(4.961,-5.118) 15(5.461,1.054) 16(5.461,-5.118) 17(5.961,1.054) 18(5.961,-5.118) 19(6.462,1.054) 20(6.462,-5.118) 21(6.962,1.054) 22(6.962,-5.118) 23(7.463,1.054) 24(7.463,-5.118) 25(7.963,1.054) 26(7.963,-5.118) 27(8.463,1.054) 28(8.463,-5.118) 29(8.964,1.054) 30(8.964,-5.118) 31(9.464,1.054) 32(9.464,-5.118) 33(9.964,1.054) 34(9.964,-5.118) 35(10.465,1.054) 36(10.465,-5.118) 37(10.965,1.054) 38(10.965,-5.118) 39(11.466,1.054) 40(11.466,-5.118) 41(11.966,1.054) 42(11.966,-5.118) 43(12.466,1.054) 44(12.466,-5.118) 45(12.967,1.054) 46(12.967,-5.118) 47(13.467,1.054) 48(13.467,-5.118) 49(13.967,1.054) 50(13.967,-5.118) 51(14.468,1.054) 52(14.468,-5.118) 53(14.968,1.054) 54(14.968,-5.118) 55(15.469,1.054) 56(15.469,-5.118) 57(15.969,1.054) 58(15.969,-5.118) 59(16.469,1.054) 60(16.469,-5.118) 61(21.961,1.054) 62(21.961,-5.118) 63(22.461,1.054) 64(22.461,-5.118) 65(22.962,1.054) 66(22.962,-5.118) 67(23.462,1.054) 68(23.462,-5.118) 69(23.962,1.054) 70(23.962,-5.118) 71(24.463,1.054) 72(24.463,-5.118) 73(24.963,1.054) 74(24.963,-5.118) 75(25.463,1.054) 76(25.463,-5.118) 77(25.964,1.054) 78(25.964,-5.118) 79(26.464,1.054) 80(26.464,-5.118) 81(26.965,1.054) 82(26.965,-5.118) 83(27.465,1.054) 84(27.465,-5.118) 85(27.965,1.054) 86(27.965,-5.118) 87(28.466,1.054) 88(28.466,-5.118) 89(28.966,1.054) 90(28.966,-5.118) 91(29.467,1.054) 92(29.467,-5.118) 93(29.967,1.054) 94(29.967,-5.118) 95(30.467,1.054) 96(30.467,-5.118) 97(30.968,1.054) 98(30.968,-5.118) 99(31.468,1.054) 100(31.468,-5.118) 101(31.968,1.054) 102(31.968,-5.118) 103(32.469,1.054) 104(32.469,-5.118) 105(32.969,1.054) 106(32.969,-5.118) 107(33.47,1.054) 108(33.47,-5.118) 109(33.97,1.054) 110(33.97,-5.118) 111(34.47,1.054) 112(34.47,-5.118) 113(34.971,1.054) 114(34.971,-5.118) 115(35.471,1.054) 116(35.471,-5.118) 117(35.971,1.054) 118(35.971,-5.118) 119(36.472,1.054) 120(36.472,-5.118) 121(41.963,1.054) 122(41.963,-5.118) 123(42.464,1.054) 124(42.464,-5.118) 125(42.964,1.054) 126(42.964,-5.118) 127(43.464,1.054) 128(43.464,-5.118) 129(43.965,1.054) 130(43.965,-5.118) 131(44.465,1.054) 132(44.465,-5.118) 133(44.966,1.054) 134(44.966,-5.118) 135(45.466,1.054) 136(45.466,-5.118) 137(45.966,1.054) 138(45.966,-5.118) 139(46.467,1.054) 140(46.467,-5.118) 141(46.967,1.054) 142(46.967,-5.118) 143(47.468,1.054) 144(47.468,-5.118) 145(47.968,1.054) 146(47.968,-5.118) 147(48.468,1.054) 148(48.468,-5.118) 149(48.969,1.054) 150(48.969,-5.118) 151(49.469,1.054) 152(49.469,-5.118) 153(49.969,1.054) 154(49.969,-5.118) 155(50.47,1.054) 156(50.47,-5.118) 157(50.97,1.054) 158(50.97,-5.118) 159(51.471,1.054) 160(51.471,-5.118) 161(51.971,1.054) 162(51.971,-5.118) 163(52.471,1.054) 164(52.471,-5.118) 165(52.972,1.054) 166(52.972,-5.118) 167(53.472,1.054) 168(53.472,-5.118) 169(53.972,1.054) 170(53.972,-5.118) 171(54.473,1.054) 172(54.473,-5.118) 173(54.973,1.054) 174(54.973,-5.118) 175(55.474,1.054) 176(55.474,-5.118) 177(55.974,1.054) 178(55.974,-5.118) 179(56.474,1.054) 180(56.474,-5.118)
  rect 2.54x0.635 smd: 181(0.765,-2.032) 184(17.656,-2.032) 185(20.767,-2.032) 188(37.658,-2.032) 189(40.77,-2.032) 192(57.661,-2.032)
  rect 4.699x0.635 smd: 182(6.035,-2.032) 183(12.385,-2.032) 186(26.038,-2.032) 187(32.388,-2.032) 190(46.04,-2.032) 191(52.39,-2.032)
DBV5
  rect 1.4x0.5 smd: 1(-1.1,0.95) 2(-1.1,0) 3(-1.1,-0.95) 4(1.1,-0.95) 5(1.1,0.95)
HDR2X2_100CTR
  round 1.524 hole 0.889: 1(0,0) 2(0,-2.54) 3(2.54,0) 4(2.54,-2.54)
HDR_THVT_1X2_100_M
  rect 1.473x1.473 hole 0.965: 1(0,0)
  round 1.473 hole 0.965: 2(0,-2.54)
HDR_THVT_1X3_100_M
  rect 1.575x1.575 hole 1.016: 1(0,0)
  round 1.575 hole 1.016: 2(0,-2.54) 3(0,-5.08)
LED_0805
  rect 1.422x1.524 smd: 1(-1.143,0) 2(1.143,0)
LPS3015
  custom 0.286x0.286 smd: 1(-1.143,0) 2(1.143,0)
OSC_4_SM_460X386
  rect 1.524x2.032 smd: 1(-3.81,-4.2) 4(3.81,-4.2) 5(3.81,4.2) 8(-3.81,4.2)
QFN10_RSW
  rect 0.889x0.254 smd: 1(-0.827,0.2) 2(-0.827,-0.2) 6(0.827,-0.2) 7(0.827,0.2)
  rect 0.254x0.889 smd: 3(-0.4,-1.002) 4(0,-1.002) 5(0.4,-1.002) 8(0.4,1.002) 9(0,1.002) 10(-0.4,1.002)
QFN24_RGE_RTW
  custom 0.076x0.076 smd: 1(-2.07,1.25) 2(-2.07,0.75) 3(-2.07,0.25) 4(-2.07,-0.25) 5(-2.07,-0.75) 6(-2.07,-1.25) 7(-1.25,-2.07) 8(-0.75,-2.07) 9(-0.25,-2.07) 10(0.25,-2.07) 11(0.75,-2.07) 12(1.25,-2.07) 13(2.07,-1.25) 14(2.07,-0.75) 15(2.07,-0.25) 16(2.07,0.25) 17(2.07,0.75) 18(2.07,1.25) 19(1.25,2.07) 20(0.75,2.07) 21(0.25,2.07) 22(-0.25,2.07) 23(-0.75,2.07) 24(-1.25,2.07)
  rect 2.54x2.54 smd: 25(0,0)
QFN48_RGZ_RTC
  custom 0.076x0.076 smd: 1(-3.525,2.75) 2(-3.525,2.25) 3(-3.525,1.75) 4(-3.525,1.25) 5(-3.525,0.75) 6(-3.525,0.25) 7(-3.525,-0.25) 8(-3.525,-0.75) 9(-3.525,-1.25) 10(-3.525,-1.75) 11(-3.525,-2.25) 12(-3.525,-2.75) 13(-2.75,-3.525) 14(-2.25,-3.525) 15(-1.75,-3.525) 16(-1.25,-3.525) 17(-0.75,-3.525) 18(-0.25,-3.525) 19(0.25,-3.525) 20(0.75,-3.525) 21(1.25,-3.525) 22(1.75,-3.525) 23(2.25,-3.525) 24(2.75,-3.525) 25(3.525,-2.75) 26(3.525,-2.25) 27(3.525,-1.75) 28(3.525,-1.25) 29(3.525,-0.75) 30(3.525,-0.25) 31(3.525,0.25) 32(3.525,0.75) 33(3.525,1.25) 34(3.525,1.75) 35(3.525,2.25) 36(3.525,2.75) 37(2.75,3.525) 38(2.25,3.525) 39(1.75,3.525) 40(1.25,3.525) 41(0.75,3.525) 42(0.25,3.525) 43(-0.25,3.525) 44(-0.75,3.525) 45(-1.25,3.525) 46(-1.75,3.525) 47(-2.25,3.525) 48(-2.75,3.525)
  rect 4.826x4.826 smd: 49(0,0)
SC70_DCK_G5
  rect 0.889x0.305 smd: 1(-0.95,0.65) 2(-0.95,0) 3(-0.95,-0.65) 4(0.95,-0.65) 5(0.95,0.65)
SMA_SMEL_218X247_096
  rect 0.381x1.27 smd: 1(0,-0.635)
  round 1.346 hole 1.143: 2(-1.219,-1.753) 3(1.219,-1.753) 4(-1.219,-3.962) 5(1.219,-3.962)
SMA_THVT_312X312
  round 2.337 hole 1.575: 1(0,0)
  round 2.464 hole 1.702: 2(-2.54,2.54) 3(2.54,2.54) 4(2.54,-2.54) 5(-2.54,-2.54)
SMD_XTAL_7X5MM_D75ASERIES
  rect 1.295x0.762 smd: (-2.083,-1.27) (-2.083,0) (-2.083,1.27) (2.083,-1.27) (2.083,0) 8(2.083,1.27)
  rect 0.94x1.295 smd: (-1.27,3.099) 4(-1.27,-3.099) 5(1.27,-3.099) 9(1.27,3.099)
SMP_B120
  rect 0.508x1.321 smd: 1(0,-3.1)
  custom 1.3x1.3 smd: 2(0,0)
SON_8_2MMX2MM_0P65MM
  rect 0.4x0.46 smd: 1(-0.653,-0.93) 2(-0.003,-0.93) 3(0.647,-0.93) 4(0.647,0.93) 5(-0.003,0.93) 6(-0.653,0.93)
  rect 0.4x0.85 smd: 7(0.647,0.12)
  rect 1.05x1.1 smd: 8(-0.327,0)
SON_8_124X124_PWRPAD_DRB
  oval 0.838x0.279 smd: 1(-1.475,0.975) 2(-1.475,0.325) 3(-1.475,-0.325) 4(-1.475,-0.975) 5(1.475,-0.975) 6(1.475,-0.325) 7(1.475,0.325) 8(1.475,0.975)
  rect 1.651x2.388 smd: 9(0,0)
SON_DRC_10
  rect 0.864x0.305 smd: 1(-1.5,1) 2(-1.5,0.5) 3(-1.5,0) 4(-1.5,-0.5) 5(-1.5,-1) 6(1.5,-1) 7(1.5,-0.5) 8(1.5,0) 9(1.5,0.5) 10(1.5,1)
  rect 1.524x3 smd: 11(0,0)
SOT_223_6_TG
  rect 0.762x2.388 smd: 1(-3.175,-3.378) 2(-1.905,-3.378) 3(-0.635,-3.378) 4(0.635,-3.378) 5(1.905,-3.378)
  rect 3.81x2.286 smd: 6(-0.635,2.997)
SSOP_28_413X220_26
  rect 1.778x0.406 smd: 1(-3.625,4.225) 2(-3.625,3.575) 3(-3.625,2.925) 4(-3.625,2.275) 5(-3.625,1.625) 6(-3.625,0.975) 7(-3.625,0.325) 8(-3.625,-0.325) 9(-3.625,-0.975) 10(-3.625,-1.625) 11(-3.625,-2.275) 12(-3.625,-2.925) 13(-3.625,-3.575) 14(-3.625,-4.225) 15(3.625,-4.225) 16(3.625,-3.575) 17(3.625,-2.925) 18(3.625,-2.275) 19(3.625,-1.625) 20(3.625,-0.975) 21(3.625,-0.325) 22(3.625,0.325) 23(3.625,0.975) 24(3.625,1.625) 25(3.625,2.275) 26(3.625,2.925) 27(3.625,3.575) 28(3.625,4.225)
SW_SMVT_RESET
  rect 1.575x3.175 smd: 1(-1.968,2.591) 2(-1.968,-2.591) 3(1.968,2.591) 4(1.968,-2.591)
TANT_A
  rect 1.524x1.397 smd: 1(-1.283,0) 2(1.283,0)
TANT_B
  rect 1.6x2.413 smd: 1(-1.867,0) 2(1.867,0)
TESTPAD20_30
  rect 0.813x0.508 smd: 1(0,0)
TESTPOINT_62DIA
  round 2.337 hole 1.575: 1(0,0)
TFMR_6_RF_DUAL_FOOTPRINT
  rect 1.27x1.778 smd: 1(-2.54,-2.794) 2(0,-2.794) 3(2.54,-2.794) 4(2.54,2.794) 5(0,2.794) 6(-2.54,2.794)
TP_THVT_060_RND
  round 1.575 hole 0.965: 1(0,0)
TSSOP_14_201X177_26
  rect 1.778x0.406 smd: 1(-2.825,1.95) 2(-2.825,1.3) 3(-2.825,0.65) 4(-2.825,0) 5(-2.825,-0.65) 6(-2.825,-1.3) 7(-2.825,-1.95) 8(2.825,-1.95) 9(2.825,-1.3) 10(2.825,-0.65) 11(2.825,0) 12(2.825,0.65) 13(2.825,1.3) 14(2.825,1.95)
unnamed#2
  round 1.016 smd: 1(0,0)
unnamed#3
  round 2.286 hole 3.175 unplated: (0,0)

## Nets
+1.2VCLK: C38.1 C39.1 C40.1 C148.1 C238.1 C242.1 FB35.2 TP19.1(TP) U1.C12(CLKVDD#C12) U1.K12(CLKVDD#K12)
+1.2VD: C25.1 C26.1 C27.1 C28.1 C29.1 C30.1 C31.1 C32.1 C33.1 C36.1 C134.1 C233.1 FB30.3 TP15.1(TP) U1.D7(VFUSE1) U1.E5(DIGVDD#E5) U1.E6(DIGVDD#E6) U1.E7(DIGVDD#E7) U1.F5(DIGVDD#F5) U1.J5(DIGVDD#J5) U1.K5(DIGVDD#K5) U1.K6(DIGVDD#K6) U1.K7(DIGVDD#K7) U1.L7(VFUSE2)
+1.2VDAC: C13.1 C14.1 C15.1 C16.1 C17.1 C18.1 C19.1 C20.1 C21.1 C23.1 C24.1 C147.1 C170.1 C243.1 FB34.2 TP18.1(TP) U1.D9(DACDVDD#D9) U1.E9(DACDVDD#E9) U1.E10(DACDVDD#E10) U1.F10(DACDVDD#F10) U1.G10(DACDVDD#G10) U1.H10(DACDVDD#H10) U1.J10(DACDVDD#J10) U1.K9(DACDVDD#K9) U1.K10(DACDVDD#K10) U1.L9(DACDVDD#L9)
+3.3V_LOGIC: C139.1 C141.1 FB24.2 U4.6(VCCB) U5.6(VCCB)
+3.3VA: C5.1 C6.1 C7.1 C8.1 C9.1 C10.1 C11.1 C12.1 C22.1 FB1.2 FB22.1 R145.1 R147.2 TP16.1(TP) U1.D10(AVDD33#D10) U1.E11(AVDD33#E11) U1.F11(AVDD33#F11) U1.G11(AVDD33#G11) U1.H11(AVDD33#H11) U1.J11(AVDD33#J11) U1.K11(AVDD33#K11) U1.L10(AVDD33#L10)
+3.3VCLK: C102.1 C103.1 C104.1 C118.1 C127.1 C128.1 C179.1 C215.1 FB3.1 FB4.1 FB5.1 FB6.1 FB7.1 FB8.1 FB9.1 FB10.1 FB11.1 FB12.1 FB13.2 FB15.2 FB24.1 JP5.1(PIN1) JP6.1(PIN1) JP7.2 R47.1 R51.1 R53.1 R57.1 R60.1 R61.1 R62.1 R63.1 R68.1 R69.1 R89.1 R91.1 R166.1 R170.2 TP17.1(TP) U2.15(VCC_AUXOUT) U6.1(EN) U6.2(VDDPECL#2) U6.5(VDDPECL#5) U15.1(OUT1) U15.2(OUT2)
+3.3VD: C41.1 C42.1 C43.1 C44.1 C45.1 C46.1 FB22.2 U1.D5(IOVDD#D5) U1.D6(IOVDD#D6) U1.G5(IOVDD#G5) U1.H5(IOVDD#H5) U1.L5(IOVDD#L5) U1.L6(IOVDD#L6)
+5V_USB: C91.1 C136.1 C137.1 FB14.2 J14.1(VBUS) U20.1(EN) U20.2(IN)
GNDA: C5.2 C6.2 C7.2 C8.2 C9.2 C10.2 C11.2 C12.2 C13.2 C14.2 C15.2 C16.2 C17.2 C18.2 C19.2 C20.2 C21.2 C22.2 C23.2 C24.2 C25.2 C26.2 C27.2 C28.2 C29.2 C30.2 C31.2 C32.2 C33.2 C34.2 C35.2 C36.2 C37.2 C38.2 C39.2 C40.2 C41.2 C42.2 C43.2 C44.2 C45.2 C46.2 C47.2 C48.2 C49.2 C50.2 C51.2 C54.1 C56.2 C57.2 C58.2 C59.2 C60.2 C61.2 C62.2 C63.1 C64.1 C65.2 C66.2 C67.2 C68.2 C69.2 C70.2 C71.2 C72.2 C73.2 C74.2 C75.1 C76.2 C77.2 C78.2 C79.2 C80.2 C81.2 C82.2 C83.2 C84.2 C85.2 C86.2 C87.2 C88.2 C89.2 C90.2 C91.2 C92.2 C93.2 C94.2 C95.2 C96.2 C97.2 C98.2 C101.2 C102.2 C103.2 C104.2 C111.2 C112.2 C116.2 C117.2 C118.2 C127.2 C128.2 C133.2 C134.2 C135.2 C136.2 C137.2 C139.2 C140.2 C141.2 C142.2 C143.2 C144.2 C145.2 C146.2 C147.2 C148.2 C149.2 C152.2 C153.2 C154.2 C155.2 C161.2 C162.2 C163.2 C164.2 C165.2 C167.2 C169.2 C170.2 C178.2 C179.2 C180.2 C181.2 C182.2 C215.2 C233.2 C234.2 C237.2 C238.2 C240.2 C242.2 C243.2 C244.2 C245.2 C246.2 C247.2 C250.2 C251.1 C252.1 C253.1 C257.2 C258.2 C259.2 C260.1 C261.1 C262.1 C266.2 C267.2 C268.2 C269.1 C270.1 C271.1 C275.2 C276.2 C277.2 C278.1 C279.1 C280.1 C284.2 C285.2 C286.2 D1.2(CATHODE) D2.2(CATHODE) FB30.2 FB31.2 J1.2(SHIELD1) J1.3(SHIELD2) J1.4(SHIELD3) J1.5(SHIELD4) J2.2(SHIELD1) J2.3(SHIELD2) J2.4(SHIELD3) J2.5(SHIELD4) J3.2(SHIELD1) J3.3(SHIELD2) J3.4(SHIELD3) J3.5(SHIELD4) J4.2(SHIELD1) J4.3(SHIELD2) J4.4(SHIELD3) J4.5(SHIELD4) J5.2(SHIELD1) J5.3(SHIELD2) J5.4(SHIELD3) J5.5(SHIELD4) J6.2(SHIELD1) J6.3(SHIELD2) J6.4(SHIELD3) J6.5(SHIELD4) J7.2(SHIELD1) J7.3(SHIELD2) J7.4(SHIELD3) J7.5(SHIELD4) J8.2(SHIELD1) J8.3(SHIELD2) J8.4(SHIELD3) J8.5(SHIELD4) J9.2(GND#2) J9.3(GND#3) J9.4(GND#4) J9.5(GND#5) J10.2(SHIELD1) J11.2(SHIELD1) J12.2(SHIELD1) J13.29 J13.35 J13.65 J13.66 J13.71 J13.72 J13.77 J13.78 J13.83 J13.84 J13.89 J13.90 J13.95 J13.96 J13.101 J13.102 J13.107 J13.108 J13.113 J13.114 J13.119 J13.120 J13.125 J13.126 J13.131 J13.132 J13.137 J13.138 J13.143 J13.144 J13.149 J13.150 J13.155 J13.156 J13.161 J13.162 J13.167 J13.168 J13.173 J13.174 J13.179 J13.180 J13.181(GND#181) J13.182(GND#182) J13.183(GND#183) J13.184(GND#184) J13.185(GND#185) J13.186(GND#186) J13.187(GND#187) J13.188(GND#188) J13.189(GND#189) J13.190(GND#190) J13.191(GND#191) J13.192(GND#192) J14.5(GND) J14.6(GND1) J14.7(GND2) J14.8(GND3) J14.9(GND4) J15.2(SHIELD1) J18.2 J18.3 J19.2(SHIELD1) J20.2(SHIELD1) J21.2(SHIELD1) J22.2(SHIELD1) J23.2(SHIELD1) JP2.3(PIN3) JP3.3(PIN3) JP4.1(PIN1) JP5.3(PIN3) JP6.3(PIN3) R6.1 R9.2 R10.2 R12.2 R14.2 R18.2 R21.1 R23.2 R29.1 R31.2 R33.2 R35.2 R37.1 R39.2 R41.2 R45.2 R49.1 R50.2 R55.1 R56.2 R59.2 R64.2 R65.2 R66.2 R67.2 R71.2 R72.2 R90.2 R92.2 R94.2 R96.2 R97.2 R98.2 R103.1 R112.2 R131.2 R134.2 R151.1 R153.1 R164.1 R167.1 R168.1 R315.1 R316.1 SW1.1 SW1.2 SW2.1 SW2.2 T1.1(PRIMARY) T2.3(PRIMARY_DOT) T3.1(PRIMARY) T4.3(PRIMARY_DOT) TP1.1(TP) TP3.1(TP) TP6.1(TP) TP7.1(TP) TP8.1(TP) TP9.1(TP) TP13.1(TP) TP27.1 TP28.1 TP29.1 TP30.1 TP31.1 TP32.1 TP33.1 TP34.1 U1.A10(GND#A10) U1.A13(GND#A13) U1.A14(GND#A14) U1.B10(GND#B10) U1.B11(GND#B11) U1.B12(GND#B12) U1.B13(GND#B13) U1.C5(GND#C5) U1.C6(GND#C6) U1.C7(GND#C7) U1.C8(GND#C8) U1.C9(GND#C9) U1.C10(GND#C10) U1.C13(GND#C13) U1.D8(GND#D8) U1.D13(GND#D13) U1.D14(GND#D14) U1.E8(GND#E8) U1.E12(GND#E12) U1.E13(GND#E13) U1.F6(GND#F6) U1.F7(GND#F7) U1.F8(GND#F8) U1.F9(GND#F9) U1.F12(GND#F12) U1.F13(GND#F13) U1.G6(GND#G6) U1.G7(GND#G7) U1.G8(GND#G8) U1.G9(GND#G9) U1.G13(GND#G13) U1.G14(GND#G14) U1.H6(GND#H6) U1.H7(GND#H7) U1.H8(GND#H8) U1.H9(GND#H9) U1.H13(GND#H13) U1.H14(GND#H14) U1.J6(GND#J6) U1.J7(GND#J7) U1.J8(GND#J8) U1.J9(GND#J9) U1.J12(GND#J12) U1.J13(GND#J13) U1.K8(GND#K8) U1.K13(GND#K13) U1.L8(GND#L8) U1.L13(GND#L13) U1.L14(GND#L14) U1.M5(GND#M5) U1.M6(GND#M6) U1.M7(GND#M7) U1.M8(GND#M8) U1.M9(GND#M9) U1.M10(GND#M10) U1.M11(GND#M11) U1.M12(GND#M12) U1.M13(GND#M13) U1.N13(GND#N13) U1.P13(GND#P13) U1.P14(GND#P14) U2.2(SEC REF-) U2.36(GND_VCO) U2.43(AUX IN) U2.49(GND_PAD) U3.7(GND#7) U3.18(GND#18) U3.21(GND#21) U3.25(AGND) U3.26(TEST) U4.2(O\E\) U4.3(GND) U5.1(DIR2) U5.2(O\E\) U5.3(GND) U6.7(VSS#7) U6.8(VDD2#8) U6.11(VDD2#11) U6.13(VSS#13) U6.18(S0) U6.20(VDD0#20) U6.23(VDD0#23) U6.24(S2) U6.25(PWRPAD) U9.1(1O\E\) U9.4(2O\E\) U9.7(GND) U9.10(3O\E\) U10.3(GND) U11.8(GND) U11.11(THERMPAD) U12.3(GND#3) U12.6(GND#6) U13.2(GND) U15.4(GND) U15.9(PWRPAD) U16.4(GND) U17.4(GND) U20.3(GND#3) U20.6(GND#6) U21.2(GND) U22.2(GND)
VCC: C111.1 C112.1 C117.1 C135.1 C154.1 C155.1 C161.1 C237.1 FB20.1 R143.2 U11.2(MODE/DATA) U11.3(VIN) U11.7(EN1) U11.9(EN2) U15.5(EN) U15.7(IN2) U15.8(IN1)
VCC_AUXIN: C58.1 C61.1 FB3.2 U2.44(VCC_AUXIN)
VCC_PLL: C56.1 C57.1 C59.1 C60.1 FB4.2 U2.39(VCC2_PLL#39) U2.42(VCC2_PLL#42)
VCC_VCO: C69.1 C70.1 C71.1 C72.1 FB7.2 U2.34(VCC_VCO#34) U2.35(VCC_VCO#35)
VDD1: C62.1 C90.1 C101.1 FB15.1 U6.14(VDD1#14) U6.17(VDD1#17)
A1OUT: J8.1(CENTER) R42.2
A2OUT: J7.1(CENTER) R40.2 T4.1(PRIMARY)
ALARM: TP5.1(TP) U1.N12(ALARM)
B1OUT: J5.1(CENTER) R28.2
B2OUT: J6.1(CENTER) R32.1 T3.3(PRIMARY_DOT)
C1OUT: J4.1(CENTER) R25.2
C2OUT: J3.1(CENTER) R24.2 T2.1(PRIMARY)
CDC-PRIREF+: C53.2 R47.2 R50.1 U2.45(PRI REF+)
CDC-PRIREF-: JP4.2(PIN2) U2.46(PRI REF-)
CDC_READ: R78.2 U3.11(D3)
CDCOUT: R53.2 R54.1 R56.1 R88.2 R121.2
CDCOUT\: R57.2 R58.1 R59.1 R93.2 R120.2
D1OUT: J1.1(CENTER) R4.2
D2OUT: J2.1(CENTER) R13.1 T1.3(PRIMARY_DOT)
DA0N: J13.165 U1.G3(DA0N)
DA0P: J13.163 U1.G4(DA0P)
DA1N: J13.159 U1.F1(DA1N)
DA1P: J13.157 U1.F2(DA1P)
DA2N: J13.153 U1.F3(DA2N)
DA2P: J13.151 U1.F4(DA2P)
DA3N: J13.147 U1.E1(DA3N)
DA3P: J13.145 U1.E2(DA3P)
DA4N: J13.141 U1.E3(DA4N)
DA4P: J13.139 U1.E4(DA4P)
DA5N: J13.135 U1.D1(DA5N)
DA5P: J13.133 U1.D2(DA5P)
DA6N: J13.129 U1.D3(DA6N)
DA6P: J13.127 U1.D4(DA6P)
DA7N: J13.123 U1.C1(DA7N)
DA7P: J13.121 U1.C2(DA7P)
DA8N: J13.111 U1.C3(DA8N)
DA8P: J13.109 U1.C4(DA8P)
DA9N: J13.105 U1.B1(DA9N)
DA9P: J13.103 U1.A1(DA9P)
DA10N: J13.99 U1.B2(DA10N)
DA10P: J13.97 U1.A2(DA10P)
DA11N: J13.93 U1.B3(DA11N)
DA11P: J13.91 U1.A3(DA11P)
DA12N: J13.87 U1.B4(DA12N)
DA12P: J13.85 U1.A4(DA12P)
DA13N: J13.81 U1.B5(DA13N)
DA13P: J13.79 U1.A5(DA13P)
DA14N: J13.75 U1.B6(DA14N)
DA14P: J13.73 U1.A6(DA14P)
DA15N: J13.69 U1.B7(DA15N)
DA15P: J13.67 U1.A7(DA15P)
DAC_DACCLK: C4.1 R15.2 U1.A12(DACCLKP)
DAC_DACCLKC: C3.1 R15.1 U1.A11(DACCLKN)
DAC_FIFO_OSTR: C2.1 R5.2 U1.A9(OSTRP)
DAC_FIFO_OSTRC: C1.1 R5.1 U1.B9(OSTRN)
DAC_RESET: C47.1 R46.1 SW1.3 SW1.4 U1.N10(RESETB)
DACCLK: R62.2 R66.1 R155.1 U2.20(U1N)
DACCLKC: R63.2 R67.1 R154.1 U2.19(U1P)
DATACLK-N: J13.117 SJP10.2(PIN2)
DATACLK-P: J13.115 SJP9.2(PIN2)
DATACLKN: SJP12.2(PIN2) U1.G1(DATACLKN)
DATACLKP: SJP11.2(PIN2) U1.G2(DATACLKP)
DB0N: J13.166 U1.P7(DB0N)
DB0P: J13.164 U1.N7(DB0P)
DB1N: J13.160 U1.P6(DB1N)
DB1P: J13.158 U1.N6(DB1P)
DB2N: J13.154 U1.P5(DB2N)
DB2P: J13.152 U1.N5(DB2P)
DB3N: J13.148 U1.P4(DB3N)
DB3P: J13.146 U1.N4(DB3P)
DB4N: J13.142 U1.P3(DB4N)
DB4P: J13.140 U1.N3(DB4P)
DB5N: J13.136 U1.P2(DB5N)
DB5P: J13.134 U1.N2(DB5P)
DB6N: J13.130 U1.P1(DB6N)
DB6P: J13.128 U1.N1(DB6P)
DB7N: J13.124 U1.M1(DB7N)
DB7P: J13.122 U1.M2(DB7P)
DB8N: J13.112 U1.M3(DB8N)
DB8P: J13.110 U1.M4(DB8P)
DB9N: J13.106 U1.L1(DB9N)
DB9P: J13.104 U1.L2(DB9P)
DB10N: J13.100 U1.L3(DB10N)
DB10P: J13.98 U1.L4(DB10P)
DB11N: J13.94 U1.K1(DB11N)
DB11P: J13.92 U1.K2(DB11P)
DB12N: J13.88 U1.K3(DB12N)
DB12P: J13.86 U1.K4(DB12P)
DB13N: J13.82 U1.J1(DB13N)
DB13P: J13.80 U1.J2(DB13P)
DB14N: J13.76 U1.J3(DB14N)
DB14P: J13.74 U1.J4(DB14P)
DB15N: J13.70 U1.H3(DB15N)
DB15P: J13.68 U1.H4(DB15P)
DCLK-N: SJP10.1(PIN1) SJP12.1(PIN1)
DCLK-P: SJP9.1(PIN1) SJP11.1(PIN1)
DCLKN: SJP10.3(PIN3) SJP12.3(PIN3)
DCLKP: SJP9.3(PIN3) SJP11.3(PIN3)
EXT_LFN: C52.1 C55.1 U2.41(EXT_LFN)
EXT_LFP: C55.2 R48.1 U2.40(EXT_LFP)
EXTIO: C37.1 TP2.1(TP) U1.G12(EXTIO)
FIFO-OSTR: C100.1 R68.2 R71.1 U2.17(U2N)
FIFO-OSTRC: C99.1 R69.2 R72.1 U2.16(U2P)
FIFO_ISTRN: J13.178 U1.H1(ISTRN)
FIFO_ISTRP: J13.176 U1.H2(ISTRP)
FIFO_OSTR: R89.2 R90.1 R152.1 U6.16(/Y1)
FIFO_OSTRC: R91.2 R92.1 R149.1 U6.15(Y1)
FPGA_CLKOUT2_N: J13.33 R93.1
FPGA_CLKOUT2_P: J13.31 R88.1
FPGA_CLKOUTN: J13.118 R117.2
FPGA_CLKOUTP: J13.116 R116.2
GC_+6.0VDC: C143.1 C144.1 J13.1 J13.2 J13.3 J13.4 JP10.3(PIN3)
IO_LOGIC: C51.1 C94.1 C98.1 C138.2 C140.1 C142.1 C250.1 JP2.1(PIN1) JP3.1(PIN1) R46.2 R73.1 R74.1 R83.1 R135.1 R136.1 R137.1 TP25.1(TP) U1.L12(IOVDD2) U3.4(VCCIO) U4.1(DIR2) U4.7(VCCA) U4.10(DIR1) U5.7(VCCA) U5.10(DIR1) U9.14(VCC) U10.5(VCC) U20.4(OUT)
IOUTA1: C281.2 C284.1 L41.2 R112.1 U1.B14(IOUT1P)
IOUTA2: C278.2 C281.1 L40.2 R98.1 U1.C14(IOUT1N)
IOUTB1: C269.2 C272.1 L36.2 R97.1 U1.F14(IOUT2P)
IOUTB2: C272.2 C275.1 L37.2 R96.1 U1.E14(IOUT2N)
IOUTC1: C263.2 C266.1 L34.2 R94.1 U1.J14(IOUT3P)
IOUTC2: C261.2 C263.1 L31.2 R41.1 U1.K14(IOUT3N)
IOUTD1: C251.2 C255.1 L27.2 R35.1 U1.N14(IOUT4P)
IOUTD2: C255.2 C258.1 L29.2 R33.1 U1.M14(IOUT4N)
PARITYN: J13.172 U1.P8(PARITYN)
PARITYP: J13.170 U1.N8(PARITYP)
PLLAVDD: C48.1 C49.1 FB1.1 TP26.1(TP) U1.C11(PLLAVDD#C11) U1.D11(PLLAVDD#D11)
SCLK: JP9.1 U1.P9(SCLK)
SDENB: JP12.1 U1.P10(SDENB)
SDIO: JP13.1 U1.P11(SDIO)
SDO: JP8.1 U1.P12(SDO)
SLEEP: JP3.2(PIN2) U1.N11(SLEEP)
SPI_CLK: R85.2 U2.24(SPI_CLK)
SPI_LE: R139.2 U2.25(SPI_LE)
SPI_MISO: R140.2 U2.22(SPI_MISO)
SPI_MOSI: R138.2 U2.23(SPI_MOSI)
SYNCN: R157.2 U1.B8(SYNCN)
SYNCP: R156.2 U1.A8(SYNCP)
TCXO_VCC: C178.1 C181.1 C182.1 FB25.1 R165.2 U16.9(VDD) U17.8(VDD)
TEST: TP4.1(TP) U1.L11(TESTMODE)
TXENABLE: JP2.2(PIN2) U1.N9(TXENABLE)
USB RESET: C50.1 SW2.3 SW2.4 U3.19(RESET)
VBB: R70.2 U6.6(VBB)
N24210609: C253.2 C254.1 L28.1 R6.2 R7.1 R104.1
N26666012: R44.1 U1.H12(RBIAS)
N26793352: C34.1 R43.2
N26794794: C35.1 R43.1 R133.1
N26951427: R25.1 T2.4(SECONDARY_DOT) T9.6(PRIMARY_DOT)
N26951636: R20.1 T2.6(SECONDARY) T9.4(PRIMARY)
N26951698: C262.2 C265.1 L32.1 R21.2 R22.1 R106.1
N26961459: R34.1 T3.4(SECONDARY_DOT) T10.6(PRIMARY_DOT)
N26961634: R32.2 R34.2
N26961668: R28.1 T3.6(SECONDARY) T10.4(PRIMARY)
N26961730: C271.2 C274.1 L35.1 R29.2 R30.1 R108.1
N26965899: C280.2 C283.1 L39.1 R37.2 R38.1 R110.1
N27066000: R44.2 R45.1
